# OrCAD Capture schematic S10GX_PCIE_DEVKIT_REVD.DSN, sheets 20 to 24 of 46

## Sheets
20 Flash Memory: size C
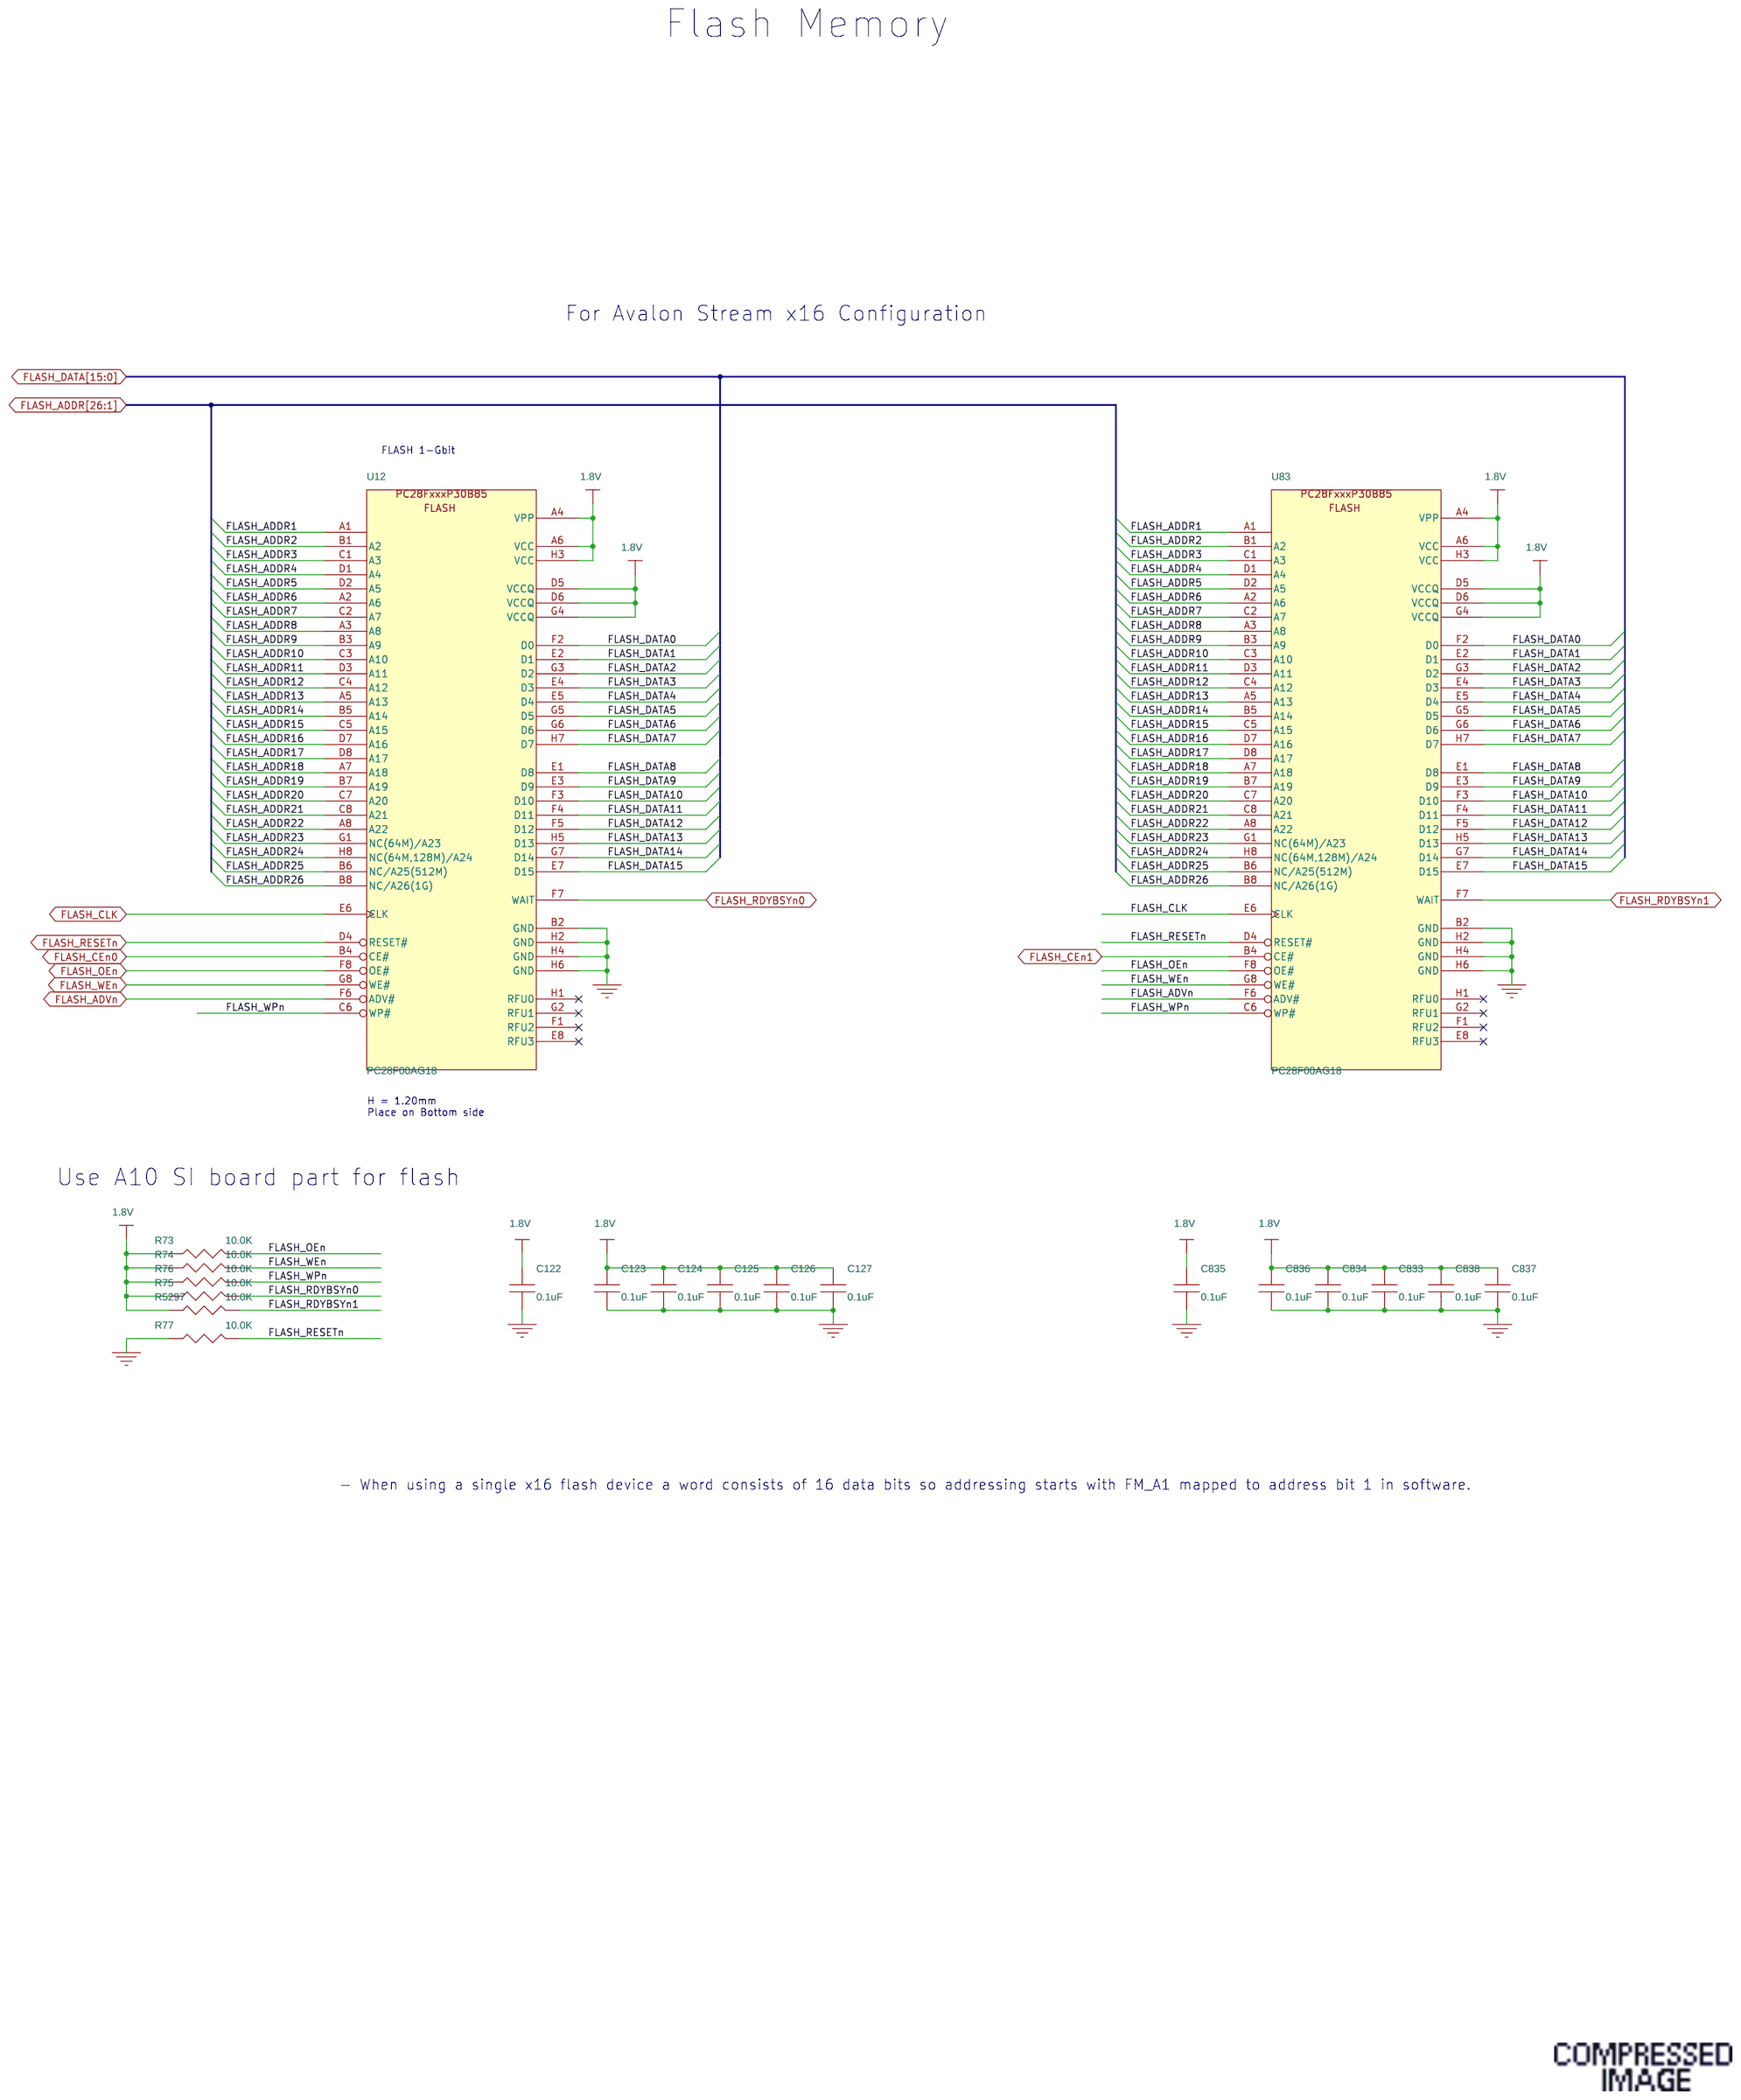
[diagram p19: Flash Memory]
21 10/100/1000 Ethernet Phy: size C
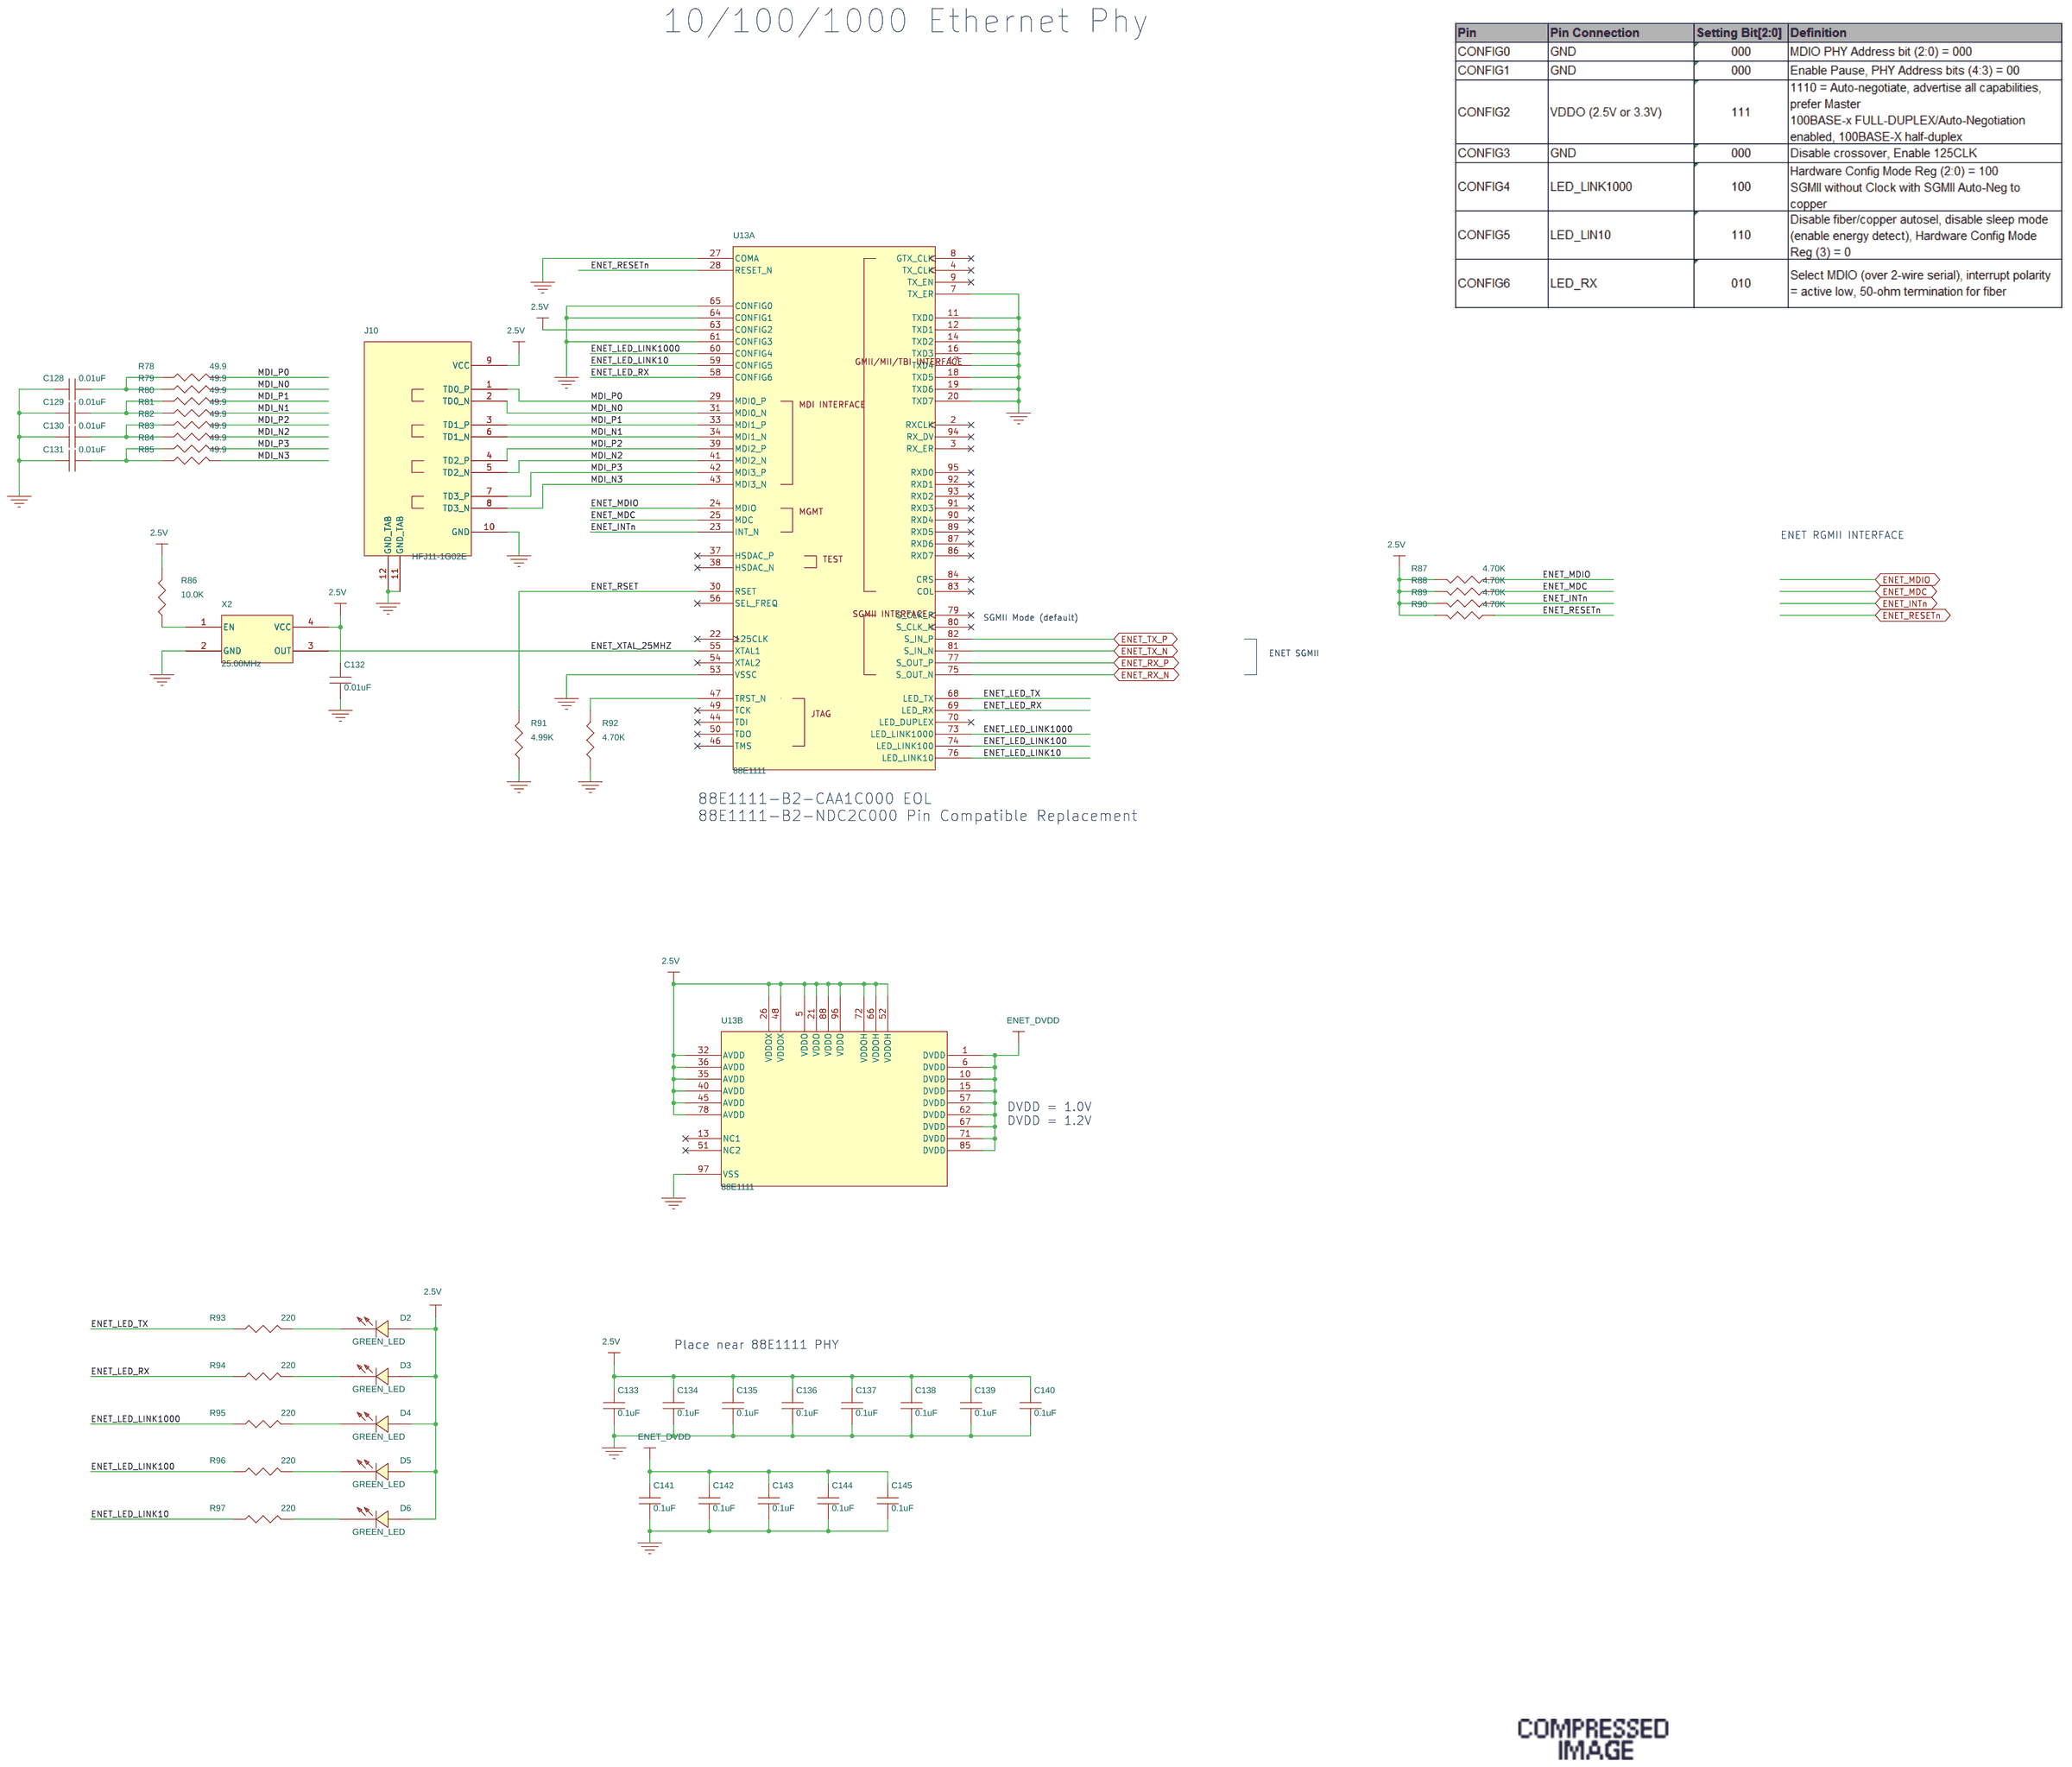
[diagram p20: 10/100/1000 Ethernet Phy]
22 HILO Connector Map
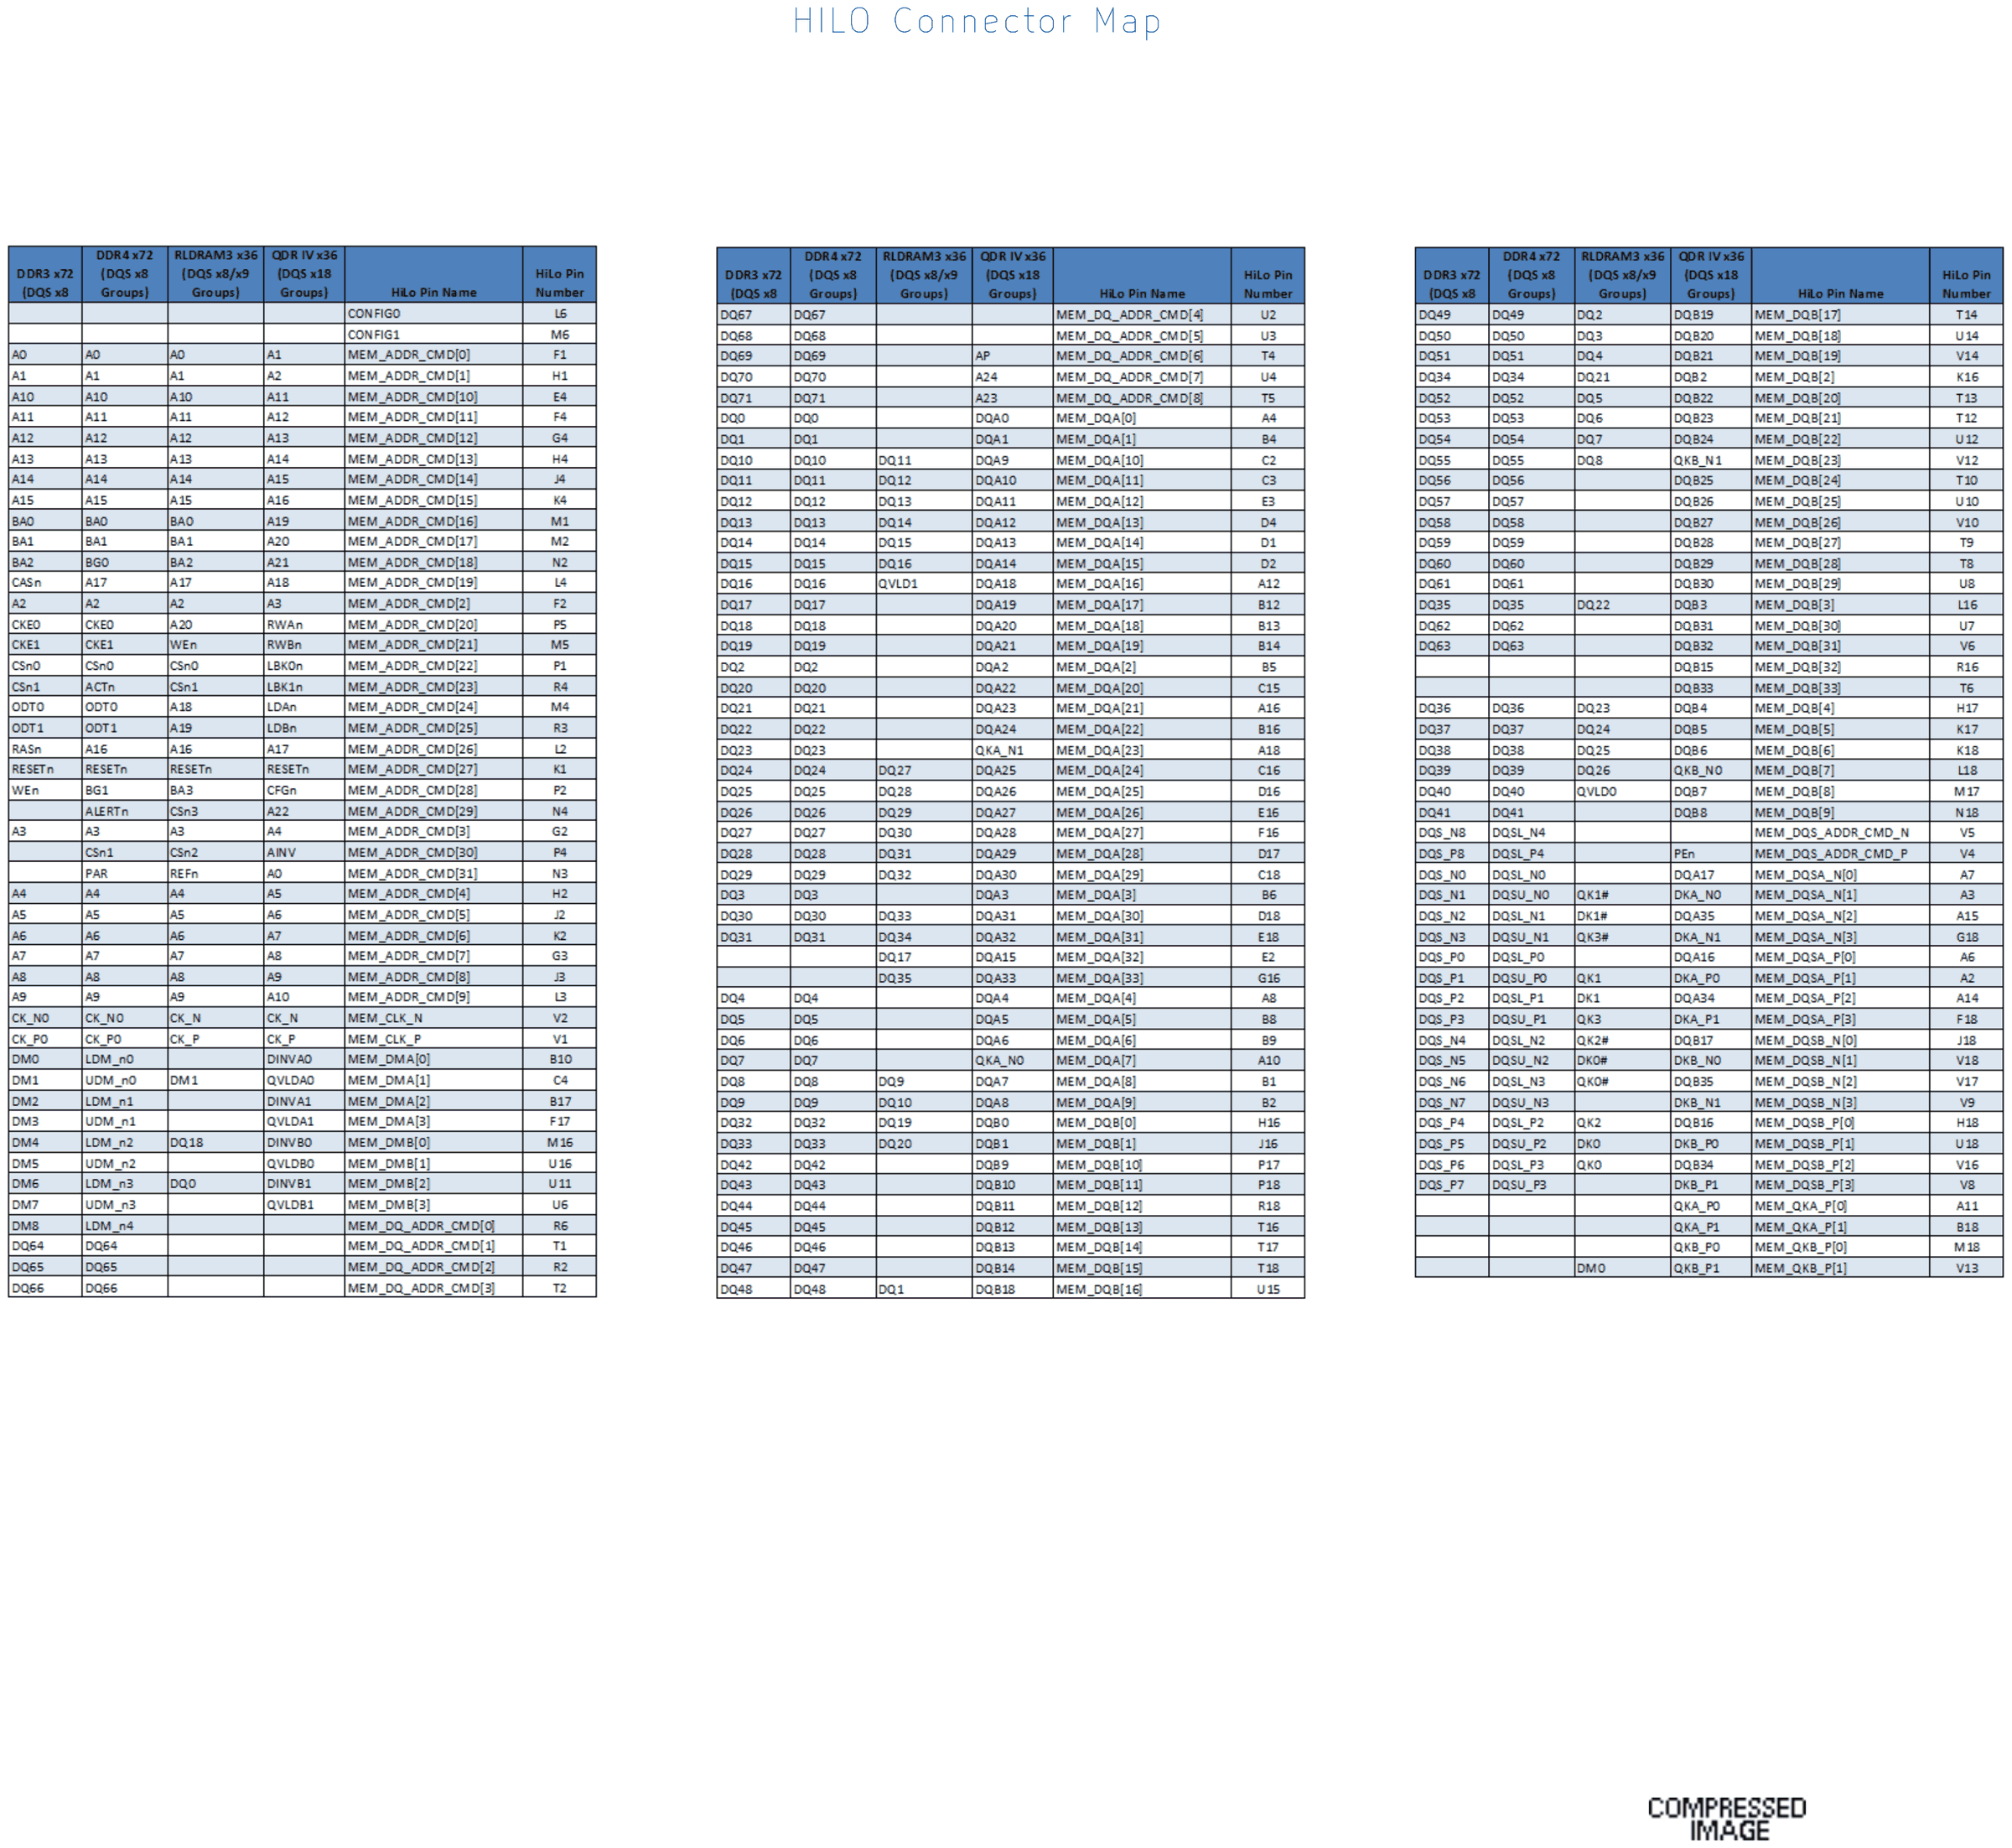
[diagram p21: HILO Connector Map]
23 HILO Memory Interface: size C
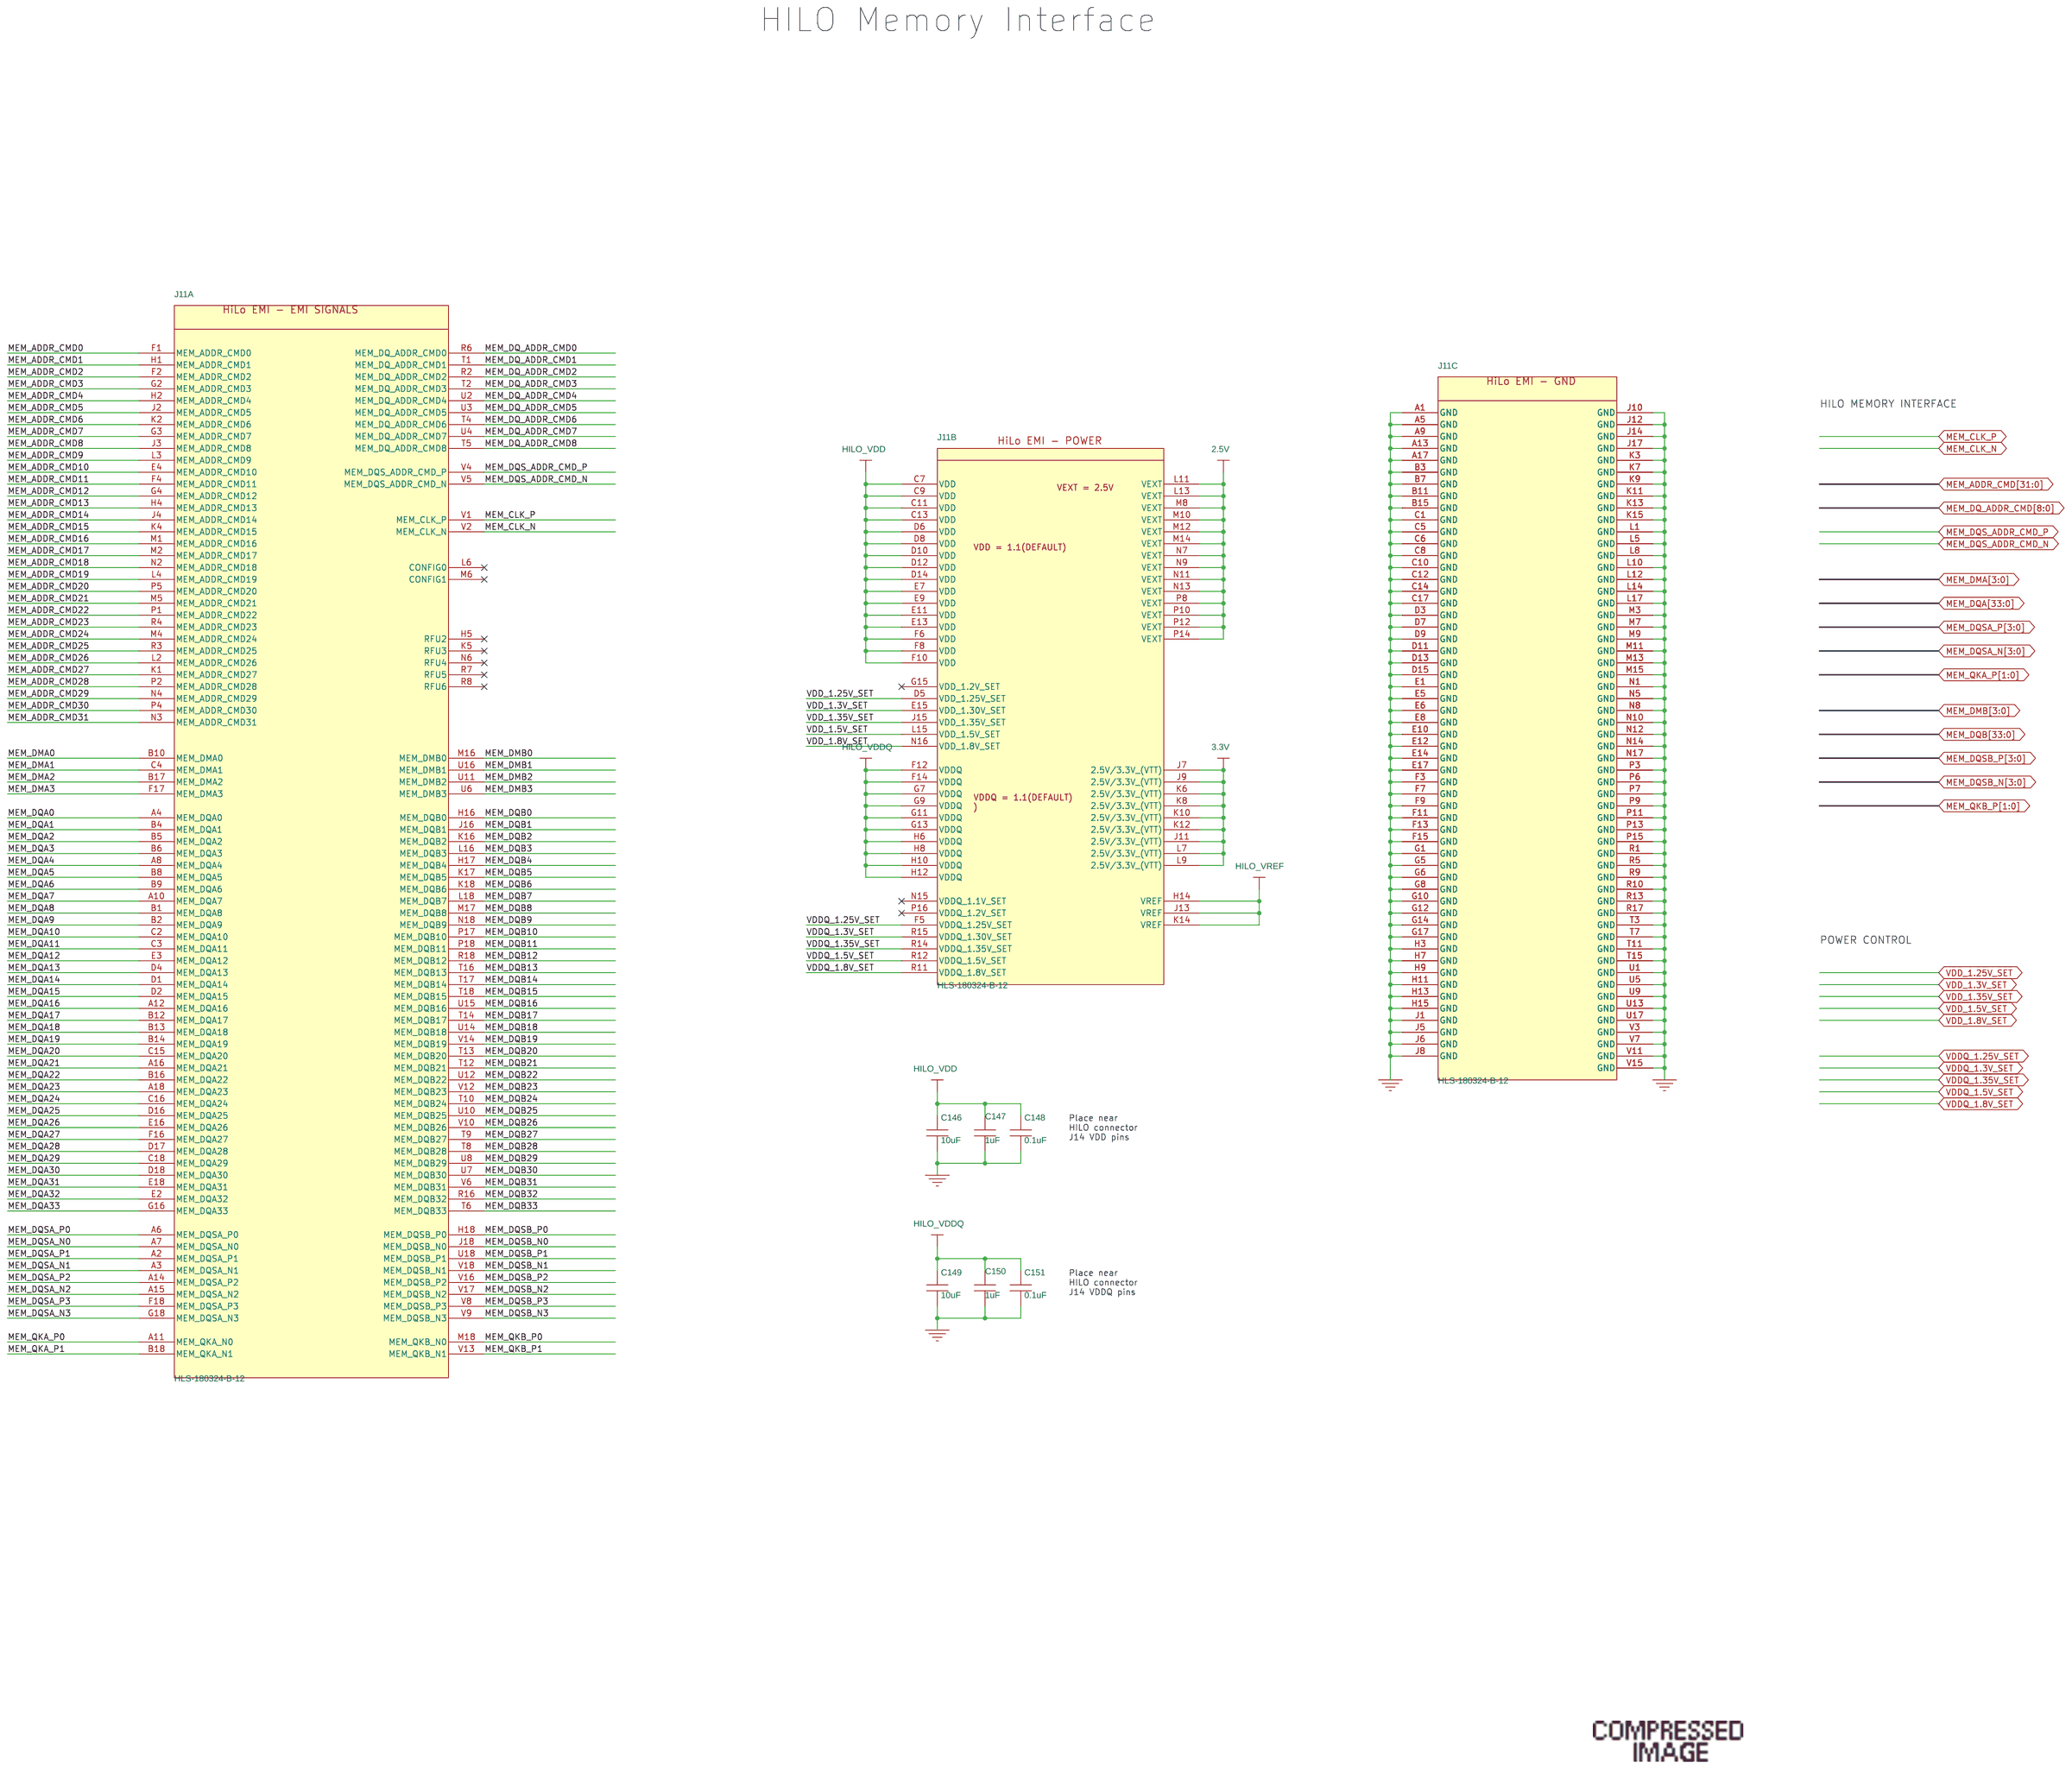
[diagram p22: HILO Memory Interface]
24 Display Port (x4): size C
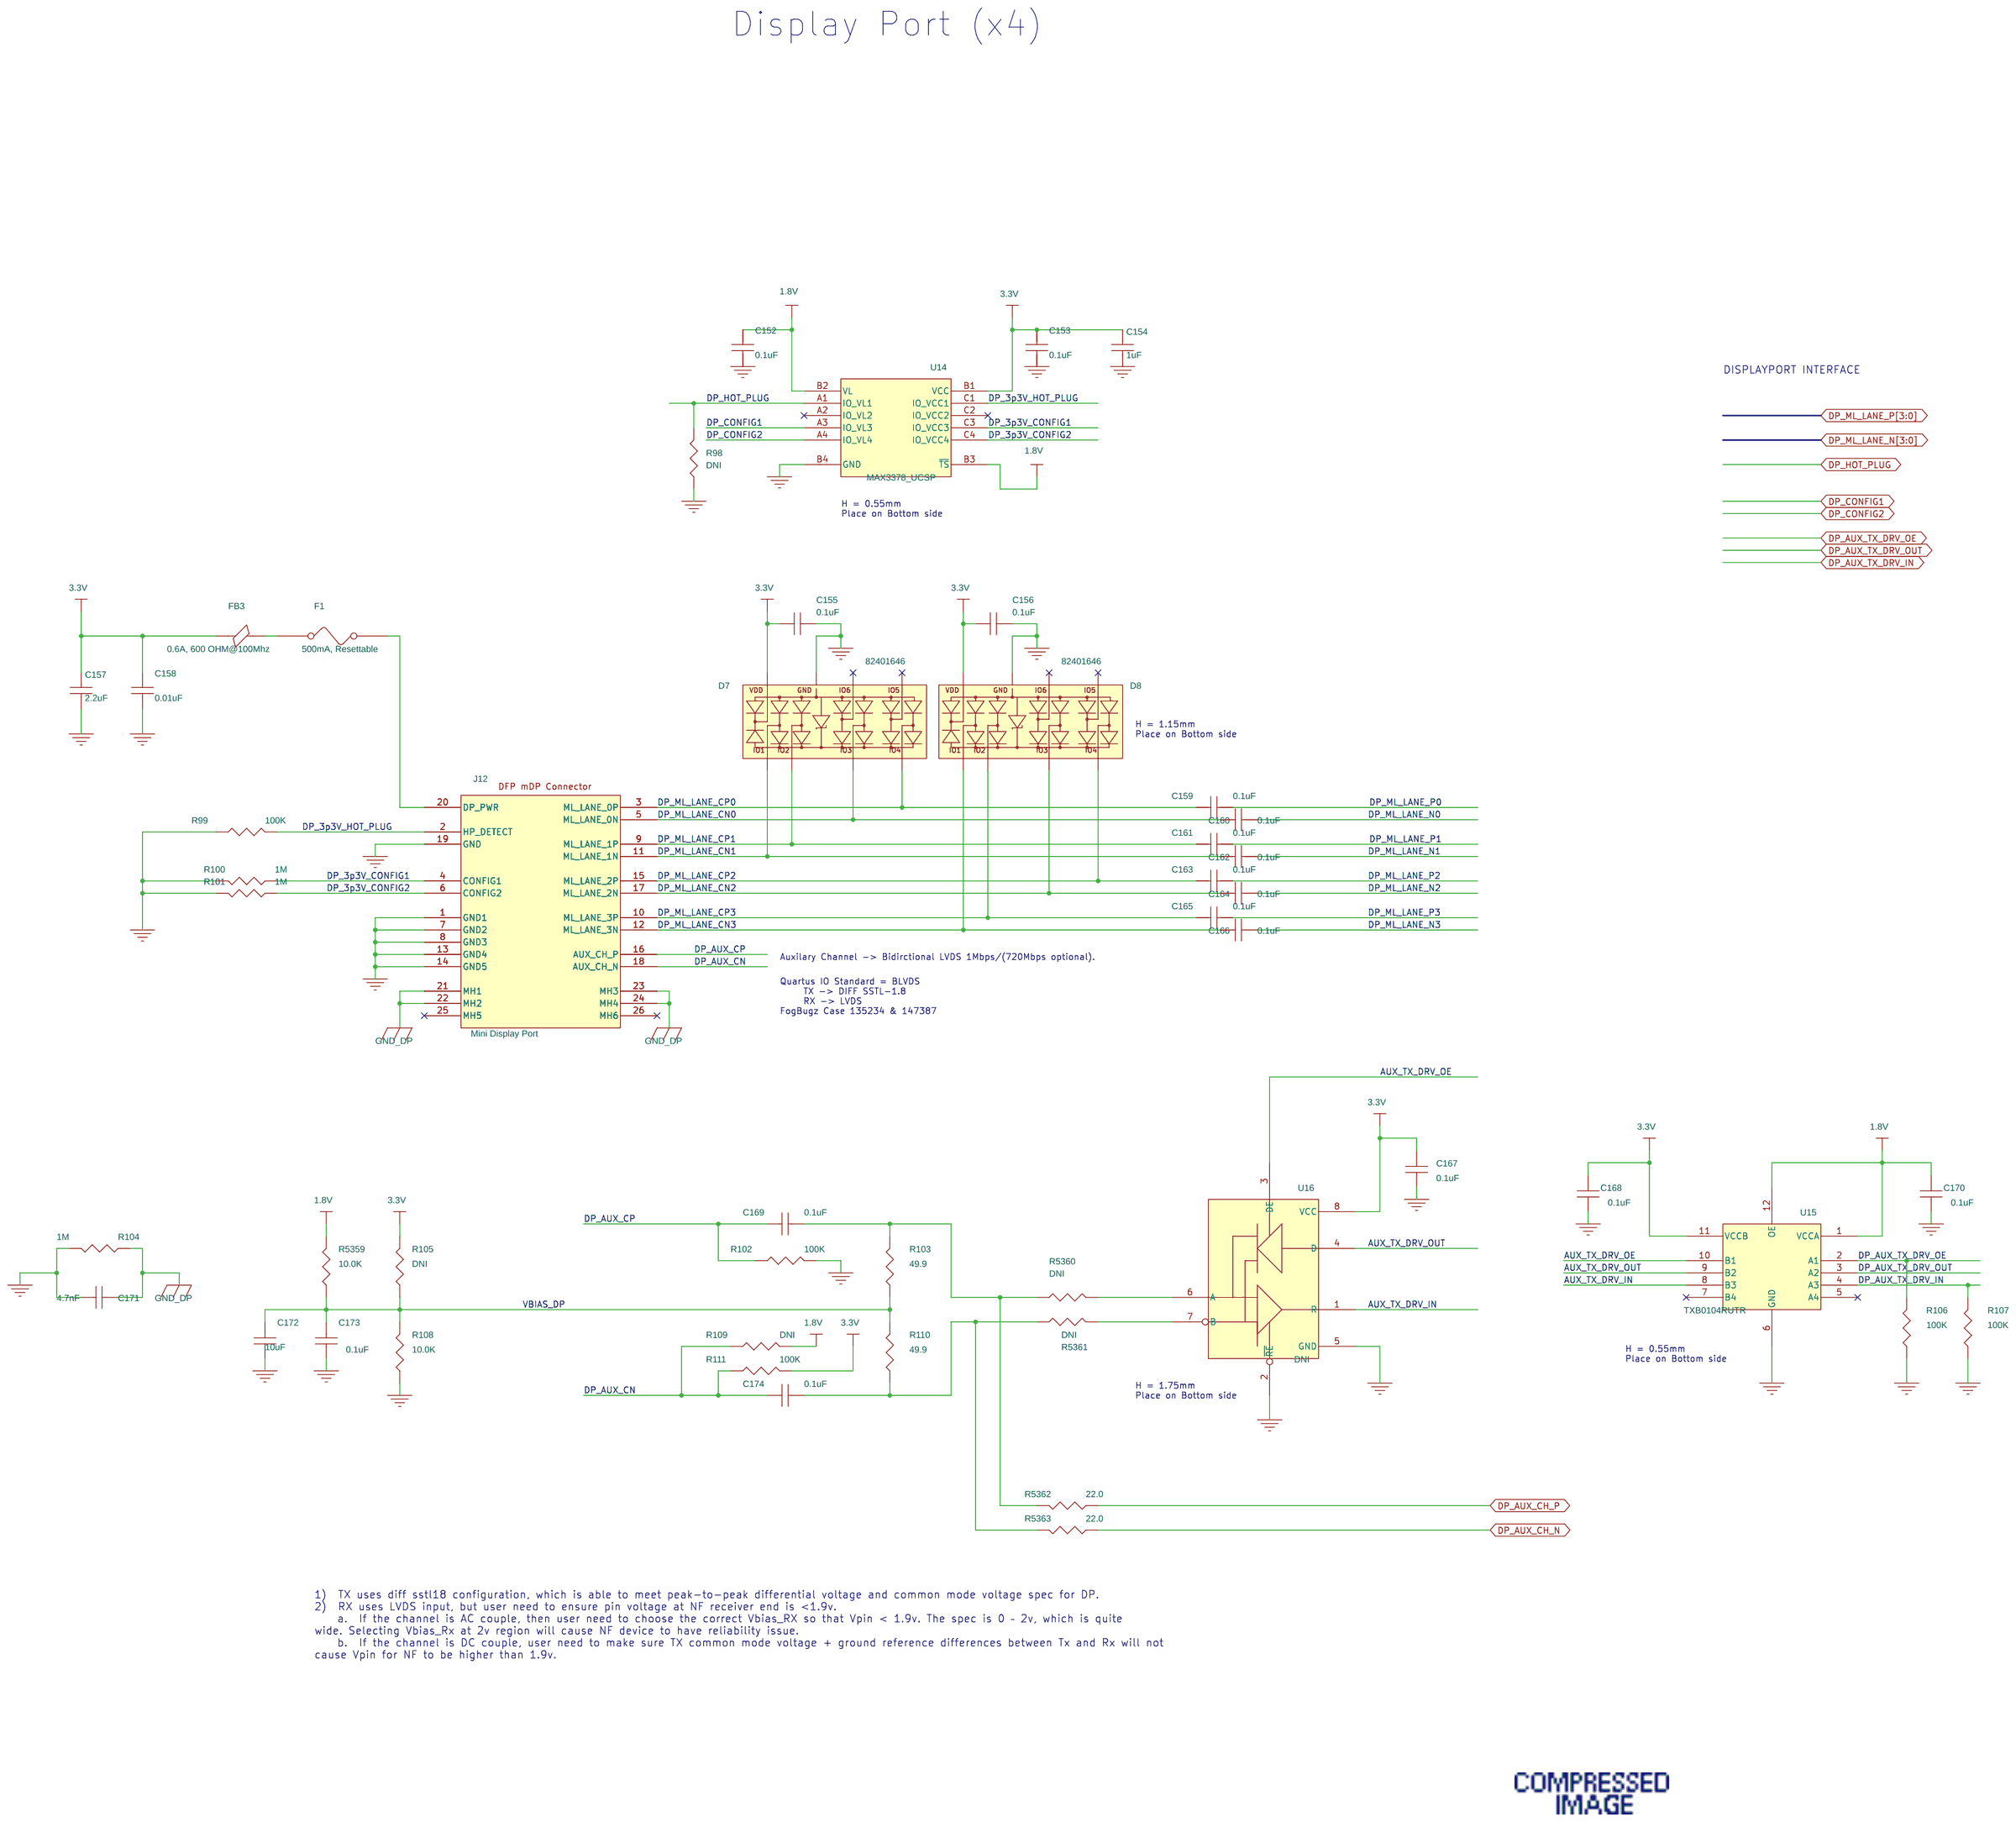
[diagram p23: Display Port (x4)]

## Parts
sheet 10/100/1000 Ethernet Phy
C128  0.01uF  [0402]
C129  0.01uF  [0402]
C130  0.01uF  [0402]
C131  0.01uF  [0402]
C132  0.01uF  [0402]
C133  0.1uF  [0402]
C134  0.1uF  [0402]
C135  0.1uF  [0402]
C136  0.1uF  [0402]
C137  0.1uF  [0402]
C138  0.1uF  [0402]
C139  0.1uF  [0402]
C140  0.1uF  [0402]
C141  0.1uF  [0402]
C142  0.1uF  [0402]
C143  0.1uF  [0402]
C144  0.1uF  [0402]
C145  0.1uF  [0402]
D2  GREEN_LED  [LED_0603]
D3  GREEN_LED  [LED_0603]
D4  GREEN_LED  [LED_0603]
D5  GREEN_LED  [LED_0603]
D6  GREEN_LED  [LED_0603]
J10  HFJ11-1G02E  [rj45]
R78  49.9  [0402]
R79  49.9  [0402]
R80  49.9  [0402]
R81  49.9  [0402]
R82  49.9  [0402]
R83  49.9  [0402]
R84  49.9  [0402]
R85  49.9  [0402]
R86  10.0K  [0402]
R87  4.70K  [0402]
R88  4.70K  [0402]
R89  4.70K  [0402]
R90  4.70K  [0402]
R91  4.99K  [0402]
R92  4.70K  [0402]
R93  220  [0402]
R94  220  [0402]
R95  220  [0402]
R96  220  [0402]
R97  220  [0402]
U13  88E1111  [BCC96]  (sections A,B)
X2  25.00MHz  [XTAL_SG310]
sheet Display Port (x4)
C152  0.1uF  [0402]
C153  0.1uF  [0402]
C154  1uF  [0402]
C155  0.1uF  [0402]
C156  0.1uF  [0402]
C157  2.2uF  [0603]
C158  0.01uF  [0402]
C159  0.1uF  [0402]
C160  0.1uF  [0402]
C161  0.1uF  [0402]
C162  0.1uF  [0402]
C163  0.1uF  [0402]
C164  0.1uF  [0402]
C165  0.1uF  [0402]
C166  0.1uF  [0402]
C167  0.1uF  [0402]
C168  0.1uF  [0402]
C169  0.1uF  [0402]
C170  0.1uF  [0402]
C171  4.7nF  [0402]
C172  10uF  [0603]
C173  0.1uF  [0402]
C174  0.1uF  [0402]
D7  82401646  [wurth_msop8]
D8  82401646  [wurth_msop8]
F1  500mA, Resettable  [0805]
FB3  0.6A, 600 OHM@100Mhz  [0805]
J12  Mini Display Port  [Mini_DP]
R98  DNI  [0402]
R99  100K  [0402]
R100  1M  [0402]
R101  1M  [0402]
R102  100K  [0402]
R103  49.9  [0402]
R104  1M  [0402]
R105  DNI  [0402]
R106  100K  [0402]
R107  100K  [0402]
R108  10.0K  [0402]
R109  DNI  [0402]
R110  49.9  [0402]
R111  100K  [0402]
R5359  10.0K  [0402]
R5360  DNI  [0402]
R5361  DNI  [0402]
R5362  22.0  [0402]
R5363  22.0  [0402]
U14  MAX3378_UCSP  [UCSP-12]
U15  TXB0104RUTR  [UPFN-12]
U16  DNI  [SOIC-8]
sheet Flash Memory
C122  0.1uF  [0402]
C123  0.1uF  [0402]
C124  0.1uF  [0402]
C125  0.1uF  [0402]
C126  0.1uF  [0402]
C127  0.1uF  [0402]
C833  0.1uF  [0402]
C834  0.1uF  [0402]
C835  0.1uF  [0402]
C836  0.1uF  [0402]
C837  0.1uF  [0402]
C838  0.1uF  [0402]
R73  10.0K  [0402]
R74  10.0K  [0402]
R75  10.0K  [0402]
R76  10.0K  [0402]
R77  10.0K  [0402]
R5297  10.0K  [0402]
U12  PC28F00AG18  [F64_10x8]
U83  PC28F00AG18  [F64_10x8]
sheet HILO Memory Interface
C146  10uF  [0603]
C147  1uF  [0402]
C148  0.1uF  [0402]
C149  10uF  [0603]
C150  1uF  [0402]
C151  0.1uF  [0402]
J11  HLS-180324-B-12  [ISI_HILO-SKT_324-KEYED]  (sections A,B,C)

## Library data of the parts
C128-C132 = CAP: CAP - CER, 10NF, 50V, +/-10%, X7R, 0402 SMD; Dielectric: X5R; Item Num: P03-16318R; Lead Free Status: Yes; Manufacturer: Murata; Manufacturer Part Num: GRM155R71H103KA88D; Manufacturer's Part No.: GRM155R71H103KA88D; Num Pins: 2; Part Class: CAPACITORS; Price: 0.07; RoHS Compliant: Yes; Tolerance: 10%
C133-C145 C155 C156 C159-C170 C173 C174 = CAP: CAP - CERAMIC,  0.1UF 0402 25VDC Y5V; AGILE_LINK: http://sj-agile9app/Agile/PLMServlet?action=OpenEmailObject&classid=10000&objid=213459527; Item Num: P03-15057R; LIFECYCLE_PHASE: Active; Lead Free Status: Lead Free; MFR_LIFECYCLE: Active; Manufacturer: Murata; Manufacturer Part Num: GRM155F51E104ZA01D; Num Pins: 2; PART_SUBCLASS: CAPACITORS; Part Class: CAPACITORS; RATED_VOLTAGE: 25V; RoHS Compliant: RoHS Compliant; TOLERANCE: +80%/-20%
D2-D6 = LED_WURTH: LED - BRIGHT GREEN, VF=2V, IF=0.03A, 0603; Item Num: P09-21344R; LIFECYCLE_PHASE: Active; Lead Free Status: Lead Free; Manufacturer: Wurth Electroniks; Manufacturer Part Num: 150060VS75000; Num Pins: 2; PART_SUBCLASS: LEDS; Part Class: LEDS; RoHS Compliant: RoHS Compliant
J10 = HFJ11-1G02E: CONN RJ-45 SINGLE PORT 10/100/1000 BASET INTEGRATED MAGNETICS 10 PIN; Item Num: P23-35065R; Lead Free Status: No; Manufacturer: Halo Electronics, Inc.; Manufacturer Part Num: HFJ11-1G02ERL; Num Pins: 10; Part Class: Connectors; Price: 10; RoHS Compliant: Yes
R78-R85 R103 R110 = RESISTOR: RES, 49.9 OHMS, 1%, 1/16W, 0402; Item Num: P02-14101R; Lead Free Status: Yes; Manufacturer: NIC Components Corp.; Manufacturer Part Num: NRC04F49R9TRF; Num Pins: 2; Part Class: Resistors; Price: 0
R73-R77 R86 R108 R5297 R5359 = RESISTOR: RES,10.0K OHMS,1.0%,1/16W, 0402; AGILE_LINK: http://sj-agile9app/Agile/PLMServlet?action=OpenEmailObject&classid=10000&objid=146548997; Item Num: P02-11364R; LIFECYCLE_PHASE: Active; Lead Free Status: No; MFR_LIFECYCLE: Active; Manufacturer: Panasonic; Manufacturer Part Num: ERJ-2RKF1002X; Num Pins: 2; PART_SUBCLASS: RESISTORS; POWER: 1/16W; RoHS Compliant: Yes; TOLERANCE: +/-1%
R87-R90 R92 = RESISTOR: RES,4.70K OHMS,1.0%,1/16W,0402; AGILE_LINK: http://sj-agile9app/Agile/PLMServlet?action=OpenEmailObject&classid=10000&objid=146753272; Item Num: P02-11384R; LIFECYCLE_PHASE: Active; Lead Free Status: No; MFR_LIFECYCLE: Active; Manufacturer: Vishay; Manufacturer Part Num: CRCW04024K70FKED; Num Pins: 2; PART_SUBCLASS: RESISTORS; POWER: 1/16W; RESISTANCE: 4.7K; RoHS Compliant: Yes; TOLERANCE: +/-1%
R91 = RESISTOR: RES 4.99K OHM 1/16W 1% 0402 SMD; Item Num: P02-14129R; Lead Free Status: Yes; Manufacturer: Panasonic; Manufacturer Part Num: ERJ-2RKF4991X; Num Pins: 2; Part Class: Resistors; Price: 0
R93-R97 = RESISTOR: RES, 220 OHMS, 5%, 1/16W, 0402; Item Num: P02-14107R; Lead Free Status: No; Manufacturer: Panasonic; Manufacturer Part Num: ERJ-2GEJ221X; Num Pins: 2; Part Class: Resistors; Price: 0
U13 = 88E1111_0: IC GIGE XCVR 10/100/1000BASE-T 2.5V 96-PIN BCC; Item Num: P01-13032R; Lead Free Status: Yes; Manufacturer: Marvell Semiconductor, Inc.; Manufacturer Part Num: 88E1111-B2-NDC2C000; Num Pins: 96; Part Class: ICs; Price: 0; RoHS Compliant: Yes
X2 = OSC_ALT: CRYSTAL, 25.000MHZ OSC, CMOS, 2.5V, SMT 3.2MM X 2.5MM, +/-50PPM; AGILE_LINK: http://sj-agile9app/Agile/PLMServlet?action=OpenEmailObject&classid=10000&objid=259526610; Item Num: P07-19194R; LIFECYCLE_PHASE: Preliminary; Lead Free Status: Lead Free; MFR_LIFECYCLE: Active; Manufacturer: Epson; Manufacturer Part Num: SG-310SDF 25.0000M-B3; Num Pins: 4; PART_SUBCLASS: CRYSTALS; RoHS Compliant: RoHS Compliant
C152 C153 = CAP: CAP - CERAMIC,  0.1UF 0402 25VDC Y5V; Dielectric: Y5V; Item Num: P03-15057R; LIFECYCLE_PHASE: Active; Lead Free Status: Lead Free; MFR_LIFECYCLE: Active; Manufacturer: Murata; Manufacturer Part Num: GRM155F51E104ZA01D; Num Pins: 2; PART_SUBCLASS: CAPACITORS; Part Class: CAPACITORS; RATED_VOLTAGE: 25V; RoHS Compliant: RoHS Compliant; Tolerance: +80%/-20%
C154 = CAP: CAP - CER, 1uF, 10V, +/-10%, X5R, 0402; Item Num: P03-15479R; Lead Free Status: Yes; Manufacturer: Murata; Manufacturer Part Num: GRM155R61A105KE15D; Num Pins: 2; Part Class: CAPACITORS; RoHS Compliant: Yes
C157 = CAP: CAP, CERAMIC, 2.2UF, 10%, 10VDC, X5R, 0603; AGILE_LINK: http://sj-agile9app/Agile/PLMServlet?action=OpenEmailObject&classid=10000&objid=256999866; Device: C40; Item Num: P03-15213R; LIFECYCLE_PHASE: Active; Lead Free Status: Lead Free; MFR_LIFECYCLE: Active; Manufacturer: Murata; Manufacturer Part Num: GRM188R61A225KE34x; Num Pins: 2; PART_SUBCLASS: CAPACITORS; RATED_VOLTAGE: 10V; RoHS Compliant: RoHS Compliant; Supplier Part Num: 490-1545-1-ND; TOLERANCE: +/-10%
C158 = CAP: CAP, CER .01UF 16V X7R 0402; AGILE_LINK: http://sj-agile9app/Agile/PLMServlet?action=OpenEmailObject&classid=10000&objid=242850622; Item Num: P03-15137R; LIFECYCLE_PHASE: Active; MFR_LIFECYCLE: Active; Manufacturer: Murata; Manufacturer Part Num: GRM155R71C103KA01D; Num Pins: 2; PACKAGING: Tape & Reel (TR); PART_SUBCLASS: CAPACITORS; RATED_VOLTAGE: 16V; RoHS Compliant: RoHS Compliant; TOLERANCE: +/-10%
C171 = CAP: CAP - CER 4700PF 50V 10% X7R 0402; AGILE_LINK: http://sj-agile9app/Agile/PLMServlet?action=OpenEmailObject&classid=10000&objid=215384813; Item Num: P03-15074R; LIFECYCLE_PHASE: Active; Lead Free Status: Lead Free; MFR_LIFECYCLE: Active; Manufacturer: Murata; Manufacturer Part Num: GRM155R71H472KA01D; Num Pins: 2; PACKAGING: Tape & Reel (TR); PART_SUBCLASS: CAPACITORS; RATED_VOLTAGE: 50V; RoHS Compliant: RoHS Compliant; Supplier Part Num: GRM155R71H472KA01D; Tolerance: +/-10%
C146 C149 C172 = CAP: CAP - CER 10UF 6.3V 20% X5R 0603; Item Num: P03-15733R; Lead Free Status: Lead Free; Manufacturer: Murata; Manufacturer Part Num: GRM188R60J106ME47X; Num Pins: 2; PART_SUBCLASS: CAPACITORS; Part Class: CAPACITORS; RoHS Compliant: RoHS Compliant
D7 D8 = 82401646: DIODE - ULTRA LOW CAPACITANCE ESD ARRAY, 0.3PF IO TO GND, 0.05PF IO TO IO, MSOP-8L; Item Num: P08-20757R; Lead Free Status: Yes; Manufacturer: Wurth; Num Pins: 8; RoHS Compliant: Yes
F1 = FUSE: FUSE - PTC RESTTBLE 0.20A 9V CHIP 0805; Item Num: P12-27075R; Lead Free Status: Yes; Manufacturer: Bel Fuse Inc; Manufacturer Part Num: 0ZCE0020FF2G; Num Pins: 2; Part Class: Fuse; Price: 0; RoHS Compliant: Yes
FB3 = BEAD_FERRITE_SM: FERRITE BEAD 600 OHM 0805 1LN; Item Num: P04-17174R; LIFECYCLE_PHASE: Active; MFR_LIFECYCLE: Active; Manufacturer: Murata; Manufacturer Part Num: BLM21AG601SN1D; Num Pins: 2; PART_SUBCLASS: INDUCTORS; Part Class: Inductors; RoHS Compliant: Yes
J12 = Mini_Display_Port: CONN - MINI-DISPLAY PORT 20-PIN RECEPTACLE, RIGHT ANGLE, SMT; Item Num: P23-38747R; Manufacturer: TE Connectivity AMP Connectors; Manufacturer Part Num: 2129320-3; Manufacturer Part Number: 2129320-3
R98 = RESISTOR: RES, 560 OHM, 5%, 1/16W, 0402, SMD; Item Num: P02-14928R; Lead Free Status: Yes; Manufacturer: Panasonic; Manufacturer Part Num: ERJ-2GEJ561x; Num Pins: 2; Part Class: RESISTORS; Price: 0; RoHS Compliant: Yes
R99 R102 R106 R107 R109 R111 = RESISTOR: RES,100K OHMS,1.0%,1/16W,0402; Item Num: P02-11386R; Lead Free Status: No; Manufacturer: Panasonic; Manufacturer Part Num: ERJ-2RKF1003X; Num Pins: 2; Part Class: Resistors; Price: 0; RoHS Compliant: Yes
R100 R101 R104 = RESISTOR: RES 1.00M OHM 1/16W 1% 0402 SMD; Item Num: P02-14034R; LIFECYCLE_PHASE: Active; Lead Free Status: Lead Free; MFR_LIFECYCLE: Active; Manufacturer: Panasonic; Manufacturer Part Num: ERJ-2RKF1004X; Num Pins: 2; Package: SMD; RoHS Compliant: RoHS Compliant; TOLERANCE: +/-1%
R105 = RESISTOR: RES,10.0K OHMS,1.0%,1/16W, 0402; AGILE_LINK: http://sj-agile9app/Agile/PLMServlet?action=OpenEmailObject&classid=10000&objid=146548997; Item Num: P02-11364R; LIFECYCLE_PHASE: Active; Lead Free Status: No; MFR_LIFECYCLE: Active; Manufacturer: Panasonic; Manufacturer Part Num: ERJ-2RKF1002X; Num Pins: 2; PART_SUBCLASS: RESISTORS; POWER: 1/16W; RESISTANCE: 10.0K; RoHS Compliant: Yes; TOLERANCE: +/-1%
R5360 R5361 = RESISTOR: RES ZERO OHM 1/16W 5% 0402 SMD; Altera Part No.: P02-14020R; Item Num: P02-14020R; LIFECYCLE_PHASE: Active; Lead Free Status: No; MFR_LIFECYCLE: Active; Manufacturer: Panasonic; Manufacturer Part Num: ERJ-2GE0R00X; Num Pins: 2; PART_SUBCLASS: RESISTORS; POWER: 1/16W; Part Class: RESISTORS; Price: 0; RESISTANCE: 0; RoHS Compliant: RoHS Compliant; Tolerance: +/-5%
R5362 R5363 = RESISTOR: RES - 22.0 OHM, 1/16W, 1%, 0402 SMD; Item Num: P02-16269R; Lead Free Status: Yes; Manufacturer: Panasonic; Manufacturer Part Num: ERJ-2RKF22R0X; Num Pins: 2; Part Class: Resistors; Price: 0
U14 = MAX3378_12UCSP: IC - QUAD LOW-VOLTAGE LEVEL TRANSLATOR, +/- 15KV, ESD-PROTECTED, 1UA, 8-16MBPS, 12-UCSP (1.5X2)MM; Item Num: P01-17875R; Lead Free Status: Yes; Manufacturer: Maxim Integrated Products, Inc.; Manufacturer Part Num: MAX3378EEBC+; Num Pins: 12; Part Class: ICs; RoHS Compliant: Yes
U15 = TXB0104RUTR: IC VOLT-LEVEL TRANSLATOR 12UQFN; Item Num: P01-18068R; Manufacturer: Texas Instruments
U16 = SN65MLVD200D: IC DIFF LINE DRVR/RCVR HS 8-SOIC; Item Num: P01-18069R; Manufacturer: Texas Instruments
C122-C127 C833-C838 = CAP: CAP - CERAMIC,  0.1UF 0402 25VDC Y5V; Dielectric: X5R; Item Num: P03-15057R; LIFECYCLE_PHASE: Active; Lead Free Status: Lead Free; Manufacturer: Murata; Manufacturer Part Num: GRM155F51E104ZA01D; Num Pins: 2; Part Class: CAPACITORS; Price: 0.07; RoHS Compliant: RoHS Compliant; Tolerance: +80%/-20%
U12 U83 = PC28FxxxP30B85_1: ICS - 1GBIT STRATA FLASH, 16-BIT DATA, VCC=VCCQ=1.7V-2.0V, 64-BALL EASY BGA (10MM X 8MM); Item Num: P01-17846R; Lead Free Status: Yes; Manufacturer: Micron; Manufacturer Part Num: PC28F00AG18FF; Num Pins: 64; Part Class: ICs; RoHS Compliant: Yes
C147 C150 = CAP: CAP - CER, 1UF, 25V, 10%, X5R, 0402; Item Num: P03-17662R; Lead Free Status: Yes; Manufacturer: TDK Electronics; Manufacturer Part Num: CGB2A1X5R1E105K033BC; Num Pins: 2; Part Class: Capacitors; Price: 0; RoHS Compliant: Yes
C148 C151 = CAP: CAP - CERAMIC,  0.1UF 0402 25VDC Y5V; Dielectric: Y5V; Item Num: P03-15057R; LIFECYCLE_PHASE: Active; Lead Free Status: Lead Free; MFR_LIFECYCLE: Active; Manufacturer: Murata; Manufacturer Part Num: GRM155F51E104ZA01D; Num Pins: 2; PART_SUBCLASS: CAPACITORS; Part Class: CAPACITORS; RATED_VOLTAGE: 25V; RoHS Compliant: RoHS Compliant; TOLERANCE: +80%/-20%
J11 = EMI_HLS-180324-B-12: CONN - HILO 324-PIN + 2-ALLIGNMENT PINS, 1MM PITCH; Item Num: P23-38580R; Lead Free Status: Yes; Manufacturer: Interconnect Systems, Inc (ISI); Num Pins: 326; Part Class: Connectors; RoHS Compliant: Yes

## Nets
1.8V: C122.1 C123.1 C124.1 C125.1 C126.1 C127.1 C152.1 C170.2 C833.1 C834.1 C835.1 C836.1 C837.1 C838.1 R73.1 R74.1 R75.1 R76.1 R109.2 R5297.1 R5359.2 U12.A4(VPP) U12.A6(VCC) U12.D5(VCCQ) U12.D6(VCCQ) U12.G4(VCCQ) U12.H3(VCC) U14.B2(VL) U14.B3(~{TS}) U15.1(VCCA) U15.12(OE) U83.A4(VPP) U83.A6(VCC) U83.D5(VCCQ) U83.D6(VCCQ) U83.G4(VCCQ) U83.H3(VCC) ; also on sheet 6 9 15 16 17 19 27 28 29 30 31 39 45
2.5V: C132.1 C133.1 C134.1 C135.1 C136.1 C137.1 C138.1 C139.1 C140.1 D2.A(ANODE) D3.A(ANODE) D4.A(ANODE) D5.A(ANODE) D6.A(ANODE) J10.9(VCC) J11.L11(VEXT) J11.L13(VEXT) J11.M8(VEXT) J11.M10(VEXT) J11.M12(VEXT) J11.M14(VEXT) J11.N7(VEXT) J11.N9(VEXT) J11.N11(VEXT) J11.N13(VEXT) J11.P8(VEXT) J11.P10(VEXT) J11.P12(VEXT) J11.P14(VEXT) R86.2 R87.2 R88.2 R89.2 R90.2 U13.5(VDDO) U13.21(VDDO) U13.26(VDDOX) U13.32(AVDD) U13.35(AVDD) U13.36(AVDD) U13.40(AVDD) U13.45(AVDD) U13.48(VDDOX) U13.52(VDDOH) U13.63(CONFIG2) U13.66(VDDOH) U13.72(VDDOH) U13.78(AVDD) U13.88(VDDO) U13.96(VDDO) X2.4(VCC) ; also on sheet 18 19 28 29 31 32 43 46
3.3V: C153.1 C154.1 C155.1 C156.1 C157.1 C158.1 C167.2 C168.2 D7.8 D8.8 FB3.2 J11.J7(2.5V/3.3V_(VTT)) J11.J9(2.5V/3.3V_(VTT)) J11.J11(2.5V/3.3V_(VTT)) J11.K6(2.5V/3.3V_(VTT)) J11.K8(2.5V/3.3V_(VTT)) J11.K10(2.5V/3.3V_(VTT)) J11.K12(2.5V/3.3V_(VTT)) J11.L7(2.5V/3.3V_(VTT)) J11.L9(2.5V/3.3V_(VTT)) R105.2 R111.2 U14.B1(VCC) U15.11(VCCB) U16.8(VCC) ; also on sheet 9 17 18 19 25 27 28 29 30 32 34
GND: C122.2 C123.2 C124.2 C125.2 C126.2 C127.2 C128.1 C129.1 C130.1 C131.1 C132.2 C133.2 C134.2 C135.2 C136.2 C137.2 C138.2 C139.2 C140.2 C141.2 C142.2 C143.2 C144.2 C145.2 C146.2 C147.2 C148.2 C149.2 C150.2 C151.2 C152.2 C153.2 C154.2 C155.2 C156.2 C157.2 C158.2 C167.1 C168.1 C170.1 C171.1 C172.1 C173.1 C833.2 C834.2 C835.2 C836.2 C837.2 C838.2 D7.7 D8.7 J10.10(GND) J10.11(GND_TAB) J10.12(GND_TAB) J11.A1(GND) J11.A5(GND) J11.A9(GND) J11.A13(GND) J11.A17(GND) J11.B3(GND) J11.B7(GND) J11.B11(GND) J11.B15(GND) J11.C1(GND) J11.C5(GND) J11.C6(GND) J11.C8(GND) J11.C10(GND) J11.C12(GND) J11.C14(GND) J11.C17(GND) J11.D3(GND) J11.D7(GND) J11.D9(GND) J11.D11(GND) J11.D13(GND) J11.D15(GND) J11.E1(GND) J11.E5(GND) J11.E6(GND) J11.E8(GND) J11.E10(GND) J11.E12(GND) J11.E14(GND) J11.E17(GND) J11.F3(GND) J11.F7(GND) J11.F9(GND) J11.F11(GND) J11.F13(GND) J11.F15(GND) J11.G1(GND) J11.G5(GND) J11.G6(GND) J11.G8(GND) J11.G10(GND) J11.G12(GND) J11.G14(GND) J11.G17(GND) J11.H3(GND) J11.H7(GND) J11.H9(GND) J11.H11(GND) J11.H13(GND) J11.H15(GND) J11.J1(GND) J11.J5(GND) J11.J6(GND) J11.J8(GND) J11.J10(GND) J11.J12(GND) J11.J14(GND) J11.J17(GND) J11.K3(GND) J11.K7(GND) J11.K9(GND) J11.K11(GND) J11.K13(GND) J11.K15(GND) J11.L1(GND) J11.L5(GND) J11.L8(GND) J11.L10(GND) J11.L12(GND) J11.L14(GND) J11.L17(GND) J11.M3(GND) J11.M7(GND) J11.M9(GND) J11.M11(GND) J11.M13(GND) J11.M15(GND) J11.N1(GND) J11.N5(GND) J11.N8(GND) J11.N10(GND) J11.N12(GND) J11.N14(GND) J11.N17(GND) J11.P3(GND) J11.P6(GND) J11.P7(GND) J11.P9(GND) J11.P11(GND) J11.P13(GND) J11.P15(GND) J11.R1(GND) J11.R5(GND) J11.R9(GND) J11.R10(GND) J11.R13(GND) J11.R17(GND) J11.T3(GND) J11.T7(GND) J11.T11(GND) J11.T15(GND) J11.U1(GND) J11.U5(GND) J11.U9(GND) J11.U13(GND) J11.U17(GND) J11.V3(GND) J11.V7(GND) J11.V11(GND) J11.V15(GND) J12.1(GND1) J12.7(GND2) J12.8(GND3) J12.13(GND4) J12.14(GND5) J12.19(GND) R77.1 R91.1 R92.1 R98.1 R99.1 R100.1 R101.1 R102.2 R104.2 R106.1 R107.1 R108.1 U12.B2(GND) U12.H2(GND) U12.H4(GND) U12.H6(GND) U13.7(TX_ER) U13.11(TXD0) U13.12(TXD1) U13.14(TXD2) U13.16(TXD3) U13.17(TXD4) U13.18(TXD5) U13.19(TXD6) U13.20(TXD7) U13.27(COMA) U13.53(VSSC) U13.61(CONFIG3) U13.64(CONFIG1) U13.65(CONFIG0) U13.97(VSS) U14.B4(GND) U15.6(GND) U16.2(~{RE}) U16.5(GND) U83.B2(GND) U83.H2(GND) U83.H4(GND) U83.H6(GND) X2.2(GND) ; also on sheet 6 7 8 9 10 11 12 13 14 15 16 17 18 19 25 27 28 29 30 31 32 33 34 35 36 37 38 39 40 41 42 43 44 45 46
GND_DP: C171.2 J12.21(MH1) J12.22(MH2) J12.23(MH3) J12.24(MH4) R104.1
VDD_1.3V_SET: J11.E15(VDD_1.30V_SET) ; also on sheet 42
VDD_1.5V_SET: J11.L15(VDD_1.5V_SET) ; also on sheet 42
VDD_1.8V_SET: J11.N16(VDD_1.8V_SET) ; also on sheet 42
VDD_1.25V_SET: J11.D5(VDD_1.25V_SET) ; also on sheet 42
VDD_1.35V_SET: J11.J15(VDD_1.35V_SET) ; also on sheet 42
VDDQ_1.3V_SET: J11.R15(VDDQ_1.30V_SET) ; also on sheet 42
VDDQ_1.5V_SET: J11.R12(VDDQ_1.5V_SET) ; also on sheet 42
VDDQ_1.8V_SET: J11.R11(VDDQ_1.8V_SET) ; also on sheet 42
VDDQ_1.25V_SET: J11.F5(VDDQ_1.25V_SET) ; also on sheet 42
VDDQ_1.35V_SET: J11.R14(VDDQ_1.35V_SET) ; also on sheet 42
AUX_TX_DRV_IN: U15.8(B3) U16.1(R)
AUX_TX_DRV_OE: U15.10(B1) U16.3(DE)
AUX_TX_DRV_OUT: U15.9(B2) U16.4(D)
DP_3p3V_CONFIG1: J12.4(CONFIG1) R100.2 U14.C3(IO_VCC3)
DP_3p3V_CONFIG2: J12.6(CONFIG2) R101.2 U14.C4(IO_VCC4)
DP_3p3V_HOT_PLUG: J12.2(HP_DETECT) R99.2 U14.C1(IO_VCC1)
DP_AUX_CH_N: R5363.1 ; also on sheet 8
DP_AUX_CH_P: R5362.1 ; also on sheet 8
DP_AUX_CN: C174.1 J12.18(AUX_CH_N) R109.1 R111.1
DP_AUX_CP: C169.1 J12.16(AUX_CH_P) R102.1
DP_AUX_TX_DRV_IN: R107.2 U15.4(A3) ; also on sheet 8
DP_AUX_TX_DRV_OE: R106.2 U15.2(A1) ; also on sheet 8
DP_AUX_TX_DRV_OUT: U15.3(A2) ; also on sheet 8
DP_CONFIG1: U14.A3(IO_VL3) ; also on sheet 8
DP_CONFIG2: U14.A4(IO_VL4) ; also on sheet 8
DP_HOT_PLUG: R98.2 U14.A1(IO_VL1) ; also on sheet 8
DP_ML_LANE_CN0: C160.1 D7.3 J12.5(ML_LANE_0N)
DP_ML_LANE_CN1: C162.1 D7.1 J12.11(ML_LANE_1N)
DP_ML_LANE_CN2: C164.1 D8.3 J12.17(ML_LANE_2N)
DP_ML_LANE_CN3: C166.1 D8.1 J12.12(ML_LANE_3N)
DP_ML_LANE_CP0: C159.1 D7.4 J12.3(ML_LANE_0P)
DP_ML_LANE_CP1: C161.1 D7.2 J12.9(ML_LANE_1P)
DP_ML_LANE_CP2: C163.1 D8.4 J12.15(ML_LANE_2P)
DP_ML_LANE_CP3: C165.1 D8.2 J12.10(ML_LANE_3P)
DP_ML_LANE_N0: C160.2 ; also on sheet 11
DP_ML_LANE_N1: C162.2 ; also on sheet 11
DP_ML_LANE_N2: C164.2 ; also on sheet 11
DP_ML_LANE_N3: C166.2 ; also on sheet 11
DP_ML_LANE_P0: C159.2 ; also on sheet 11
DP_ML_LANE_P1: C161.2 ; also on sheet 11
DP_ML_LANE_P2: C163.2 ; also on sheet 11
DP_ML_LANE_P3: C165.2 ; also on sheet 11
ENET_DVDD: C141.1 C142.1 C143.1 C144.1 C145.1 U13.1(DVDD) U13.6(DVDD) U13.10(DVDD) U13.15(DVDD) U13.57(DVDD) U13.62(DVDD) U13.67(DVDD) U13.71(DVDD) U13.85(DVDD) ; also on sheet 43
ENET_INTn: R89.1 U13.23(INT_N) ; also on sheet 6
ENET_LED_LINK10: R97.1 U13.59(CONFIG5) U13.76(LED_LINK10)
ENET_LED_LINK100: R96.1 U13.74(LED_LINK100)
ENET_LED_LINK1000: R95.1 U13.60(CONFIG4) U13.73(LED_LINK1000)
ENET_LED_RX: R94.1 U13.58(CONFIG6) U13.69(LED_RX)
ENET_LED_TX: R93.1 U13.68(LED_TX)
ENET_MDC: R88.1 U13.25(MDC) ; also on sheet 6
ENET_MDIO: R87.1 U13.24(MDIO) ; also on sheet 6
ENET_RESETn: R90.1 U13.28(RESET_N) ; also on sheet 6
ENET_RSET: R91.2 U13.30(RSET)
ENET_RX_N: U13.75(S_OUT_N) ; also on sheet 8
ENET_RX_P: U13.77(S_OUT_P) ; also on sheet 8
ENET_TX_N: U13.81(S_IN_N) ; also on sheet 8
ENET_TX_P: U13.82(S_IN_P) ; also on sheet 8
ENET_XTAL_25MHZ: U13.55(XTAL1) X2.3(OUT)
FLASH_ADDR1: U12.A1 U83.A1 ; also on sheet 7 19
FLASH_ADDR2: U12.B1(A2) U83.B1(A2) ; also on sheet 7 19
FLASH_ADDR3: U12.C1(A3) U83.C1(A3) ; also on sheet 7 19
FLASH_ADDR4: U12.D1(A4) U83.D1(A4) ; also on sheet 7 19
FLASH_ADDR5: U12.D2(A5) U83.D2(A5) ; also on sheet 7 19
FLASH_ADDR6: U12.A2(A6) U83.A2(A6) ; also on sheet 7 19
FLASH_ADDR7: U12.C2(A7) U83.C2(A7) ; also on sheet 7 19
FLASH_ADDR8: U12.A3(A8) U83.A3(A8) ; also on sheet 7 19
FLASH_ADDR9: U12.B3(A9) U83.B3(A9) ; also on sheet 7 19
FLASH_ADDR10: U12.C3(A10) U83.C3(A10) ; also on sheet 7 19
FLASH_ADDR11: U12.D3(A11) U83.D3(A11) ; also on sheet 7 19
FLASH_ADDR12: U12.C4(A12) U83.C4(A12) ; also on sheet 7 19
FLASH_ADDR13: U12.A5(A13) U83.A5(A13) ; also on sheet 7 19
FLASH_ADDR14: U12.B5(A14) U83.B5(A14) ; also on sheet 7 19
FLASH_ADDR15: U12.C5(A15) U83.C5(A15) ; also on sheet 7 19
FLASH_ADDR16: U12.D7(A16) U83.D7(A16) ; also on sheet 7 19
FLASH_ADDR17: U12.D8(A17) U83.D8(A17) ; also on sheet 7 19
FLASH_ADDR18: U12.A7(A18) U83.A7(A18) ; also on sheet 7 19
FLASH_ADDR19: U12.B7(A19) U83.B7(A19) ; also on sheet 7 19
FLASH_ADDR20: U12.C7(A20) U83.C7(A20) ; also on sheet 7 19
FLASH_ADDR21: U12.C8(A21) U83.C8(A21) ; also on sheet 7 19
FLASH_ADDR22: U12.A8(A22) U83.A8(A22) ; also on sheet 7 19
FLASH_ADDR23: U12.G1(NC(64M)/A23) U83.G1(NC(64M)/A23) ; also on sheet 7 19
FLASH_ADDR24: U12.H8(NC(64M,128M)/A24) U83.H8(NC(64M,128M)/A24) ; also on sheet 7 19
FLASH_ADDR25: U12.B6(NC/A25(512M)) U83.B6(NC/A25(512M)) ; also on sheet 7 19
FLASH_ADDR26: U12.B8(NC/A26(1G)) U83.B8(NC/A26(1G)) ; also on sheet 7 19
FLASH_ADVn: U12.F6(ADV#) U83.F6(ADV#) ; also on sheet 7 19
FLASH_CEn0: U12.B4(CE#) ; also on sheet 7 19
FLASH_CEn1: U83.B4(CE#) ; also on sheet 7 19
FLASH_CLK: U12.E6(CLK) U83.E6(CLK) ; also on sheet 7 19
FLASH_DATA0: U12.F2(D0) U83.F2(D0) ; also on sheet 7 19
FLASH_DATA1: U12.E2(D1) U83.E2(D1) ; also on sheet 7 19
FLASH_DATA2: U12.G3(D2) U83.G3(D2) ; also on sheet 7 19
FLASH_DATA3: U12.E4(D3) U83.E4(D3) ; also on sheet 7 19
FLASH_DATA4: U12.E5(D4) U83.E5(D4) ; also on sheet 7 19
FLASH_DATA5: U12.G5(D5) U83.G5(D5) ; also on sheet 7 19
FLASH_DATA6: U12.G6(D6) U83.G6(D6) ; also on sheet 7 19
FLASH_DATA7: U12.H7(D7) U83.H7(D7) ; also on sheet 7 19
FLASH_DATA8: U12.E1(D8) U83.E1(D8) ; also on sheet 7 19
FLASH_DATA9: U12.E3(D9) U83.E3(D9) ; also on sheet 7 19
FLASH_DATA10: U12.F3(D10) U83.F3(D10) ; also on sheet 7 19
FLASH_DATA11: U12.F4(D11) U83.F4(D11) ; also on sheet 7 19
FLASH_DATA12: U12.F5(D12) U83.F5(D12) ; also on sheet 7 19
FLASH_DATA13: U12.H5(D13) U83.H5(D13) ; also on sheet 7 19
FLASH_DATA14: U12.G7(D14) U83.G7(D14) ; also on sheet 7 19
FLASH_DATA15: U12.E7(D15) U83.E7(D15) ; also on sheet 7 19
FLASH_OEn: R73.2 U12.F8(OE#) U83.F8(OE#) ; also on sheet 7 19
FLASH_RDYBSYn0: R75.2 U12.F7(WAIT) ; also on sheet 7 19
FLASH_RDYBSYn1: R5297.2 U83.F7(WAIT) ; also on sheet 7 19
FLASH_RESETn: R77.2 U12.D4(RESET#) U83.D4(RESET#) ; also on sheet 7 19
FLASH_WEn: R74.2 U12.G8(WE#) U83.G8(WE#) ; also on sheet 7 19
FLASH_WPn: R76.2 U12.C6(WP#) U83.C6(WP#)
HILO_VDD: C146.1 C147.1 C148.1 J11.C7(VDD) J11.C9(VDD) J11.C11(VDD) J11.C13(VDD) J11.D6(VDD) J11.D8(VDD) J11.D10(VDD) J11.D12(VDD) J11.D14(VDD) J11.E7(VDD) J11.E9(VDD) J11.E11(VDD) J11.E13(VDD) J11.F6(VDD) J11.F8(VDD) J11.F10(VDD) ; also on sheet 42 46
HILO_VDDQ: C149.1 C150.1 C151.1 J11.F12(VDDQ) J11.F14(VDDQ) J11.G7(VDDQ) J11.G9(VDDQ) J11.G11(VDDQ) J11.G13(VDDQ) J11.H6(VDDQ) J11.H8(VDDQ) J11.H10(VDDQ) J11.H12(VDDQ) ; also on sheet 42 46
HILO_VREF: J11.H14(VREF) J11.J13(VREF) J11.K14(VREF) ; also on sheet 15 45
MDI_N0: J10.2(TD0_N) R79.2 U13.31(MDI0_N)
MDI_N1: J10.6(TD1_N) R81.2 U13.34(MDI1_N)
MDI_N2: J10.5(TD2_N) R83.2 U13.41(MDI2_N)
MDI_N3: J10.8(TD3_N) R85.2 U13.43(MDI3_N)
MDI_P0: J10.1(TD0_P) R78.2 U13.29(MDI0_P)
MDI_P1: J10.3(TD1_P) R80.2 U13.33(MDI1_P)
MDI_P2: J10.4(TD2_P) R82.2 U13.39(MDI2_P)
MDI_P3: J10.7(TD3_P) R84.2 U13.42(MDI3_P)
MEM_ADDR_CMD0: J11.F1(MEM_ADDR_CMD0) ; also on sheet 8
MEM_ADDR_CMD1: J11.H1(MEM_ADDR_CMD1) ; also on sheet 8
MEM_ADDR_CMD2: J11.F2(MEM_ADDR_CMD2) ; also on sheet 8
MEM_ADDR_CMD3: J11.G2(MEM_ADDR_CMD3) ; also on sheet 8
MEM_ADDR_CMD4: J11.H2(MEM_ADDR_CMD4) ; also on sheet 8
MEM_ADDR_CMD5: J11.J2(MEM_ADDR_CMD5) ; also on sheet 8
MEM_ADDR_CMD6: J11.K2(MEM_ADDR_CMD6) ; also on sheet 8
MEM_ADDR_CMD7: J11.G3(MEM_ADDR_CMD7) ; also on sheet 8
MEM_ADDR_CMD8: J11.J3(MEM_ADDR_CMD8) ; also on sheet 8
MEM_ADDR_CMD9: J11.L3(MEM_ADDR_CMD9) ; also on sheet 8
MEM_ADDR_CMD10: J11.E4(MEM_ADDR_CMD10) ; also on sheet 8
MEM_ADDR_CMD11: J11.F4(MEM_ADDR_CMD11) ; also on sheet 8
MEM_ADDR_CMD12: J11.G4(MEM_ADDR_CMD12) ; also on sheet 8
MEM_ADDR_CMD13: J11.H4(MEM_ADDR_CMD13) ; also on sheet 8
MEM_ADDR_CMD14: J11.J4(MEM_ADDR_CMD14) ; also on sheet 8
MEM_ADDR_CMD15: J11.K4(MEM_ADDR_CMD15) ; also on sheet 8
MEM_ADDR_CMD16: J11.M1(MEM_ADDR_CMD16) ; also on sheet 8
MEM_ADDR_CMD17: J11.M2(MEM_ADDR_CMD17) ; also on sheet 8
MEM_ADDR_CMD18: J11.N2(MEM_ADDR_CMD18) ; also on sheet 8
MEM_ADDR_CMD19: J11.L4(MEM_ADDR_CMD19) ; also on sheet 8
MEM_ADDR_CMD20: J11.P5(MEM_ADDR_CMD20) ; also on sheet 8
MEM_ADDR_CMD21: J11.M5(MEM_ADDR_CMD21) ; also on sheet 8
MEM_ADDR_CMD22: J11.P1(MEM_ADDR_CMD22) ; also on sheet 8
MEM_ADDR_CMD23: J11.R4(MEM_ADDR_CMD23) ; also on sheet 8
MEM_ADDR_CMD24: J11.M4(MEM_ADDR_CMD24) ; also on sheet 8
MEM_ADDR_CMD25: J11.R3(MEM_ADDR_CMD25) ; also on sheet 8
MEM_ADDR_CMD26: J11.L2(MEM_ADDR_CMD26) ; also on sheet 8
MEM_ADDR_CMD27: J11.K1(MEM_ADDR_CMD27) ; also on sheet 8
MEM_ADDR_CMD28: J11.P2(MEM_ADDR_CMD28) ; also on sheet 8
MEM_ADDR_CMD29: J11.N4(MEM_ADDR_CMD29) ; also on sheet 8
MEM_ADDR_CMD30: J11.P4(MEM_ADDR_CMD30) ; also on sheet 8
MEM_ADDR_CMD31: J11.N3(MEM_ADDR_CMD31) ; also on sheet 8
MEM_CLK_N: J11.V2(MEM_CLK_N) ; also on sheet 8
MEM_CLK_P: J11.V1(MEM_CLK_P) ; also on sheet 8
MEM_DMA0: J11.B10(MEM_DMA0) ; also on sheet 8
MEM_DMA1: J11.C4(MEM_DMA1) ; also on sheet 8
MEM_DMA2: J11.B17(MEM_DMA2) ; also on sheet 8
MEM_DMA3: J11.F17(MEM_DMA3) ; also on sheet 8
MEM_DMB0: J11.M16(MEM_DMB0) ; also on sheet 8
MEM_DMB1: J11.U16(MEM_DMB1) ; also on sheet 8
MEM_DMB2: J11.U11(MEM_DMB2) ; also on sheet 8
MEM_DMB3: J11.U6(MEM_DMB3) ; also on sheet 8
MEM_DQ_ADDR_CMD0: J11.R6(MEM_DQ_ADDR_CMD0) ; also on sheet 8
MEM_DQ_ADDR_CMD1: J11.T1(MEM_DQ_ADDR_CMD1) ; also on sheet 8
MEM_DQ_ADDR_CMD2: J11.R2(MEM_DQ_ADDR_CMD2) ; also on sheet 8
MEM_DQ_ADDR_CMD3: J11.T2(MEM_DQ_ADDR_CMD3) ; also on sheet 8
MEM_DQ_ADDR_CMD4: J11.U2(MEM_DQ_ADDR_CMD4) ; also on sheet 8
MEM_DQ_ADDR_CMD5: J11.U3(MEM_DQ_ADDR_CMD5) ; also on sheet 8
MEM_DQ_ADDR_CMD6: J11.T4(MEM_DQ_ADDR_CMD6) ; also on sheet 8
MEM_DQ_ADDR_CMD7: J11.U4(MEM_DQ_ADDR_CMD7) ; also on sheet 8
MEM_DQ_ADDR_CMD8: J11.T5(MEM_DQ_ADDR_CMD8) ; also on sheet 8
MEM_DQA0: J11.A4(MEM_DQA0) ; also on sheet 8
MEM_DQA1: J11.B4(MEM_DQA1) ; also on sheet 8
MEM_DQA2: J11.B5(MEM_DQA2) ; also on sheet 8
MEM_DQA3: J11.B6(MEM_DQA3) ; also on sheet 8
MEM_DQA4: J11.A8(MEM_DQA4) ; also on sheet 8
MEM_DQA5: J11.B8(MEM_DQA5) ; also on sheet 8
MEM_DQA6: J11.B9(MEM_DQA6) ; also on sheet 8
MEM_DQA7: J11.A10(MEM_DQA7) ; also on sheet 8
MEM_DQA8: J11.B1(MEM_DQA8) ; also on sheet 8
MEM_DQA9: J11.B2(MEM_DQA9) ; also on sheet 8
MEM_DQA10: J11.C2(MEM_DQA10) ; also on sheet 8
MEM_DQA11: J11.C3(MEM_DQA11) ; also on sheet 8
MEM_DQA12: J11.E3(MEM_DQA12) ; also on sheet 8
MEM_DQA13: J11.D4(MEM_DQA13) ; also on sheet 8
MEM_DQA14: J11.D1(MEM_DQA14) ; also on sheet 8
MEM_DQA15: J11.D2(MEM_DQA15) ; also on sheet 8
MEM_DQA16: J11.A12(MEM_DQA16) ; also on sheet 8
MEM_DQA17: J11.B12(MEM_DQA17) ; also on sheet 8
MEM_DQA18: J11.B13(MEM_DQA18) ; also on sheet 8
MEM_DQA19: J11.B14(MEM_DQA19) ; also on sheet 8
MEM_DQA20: J11.C15(MEM_DQA20) ; also on sheet 8
MEM_DQA21: J11.A16(MEM_DQA21) ; also on sheet 8
MEM_DQA22: J11.B16(MEM_DQA22) ; also on sheet 8
MEM_DQA23: J11.A18(MEM_DQA23) ; also on sheet 8
MEM_DQA24: J11.C16(MEM_DQA24) ; also on sheet 8
MEM_DQA25: J11.D16(MEM_DQA25) ; also on sheet 8
MEM_DQA26: J11.E16(MEM_DQA26) ; also on sheet 8
MEM_DQA27: J11.F16(MEM_DQA27) ; also on sheet 8
MEM_DQA28: J11.D17(MEM_DQA28) ; also on sheet 8
MEM_DQA29: J11.C18(MEM_DQA29) ; also on sheet 8
MEM_DQA30: J11.D18(MEM_DQA30) ; also on sheet 8
MEM_DQA31: J11.E18(MEM_DQA31) ; also on sheet 8
MEM_DQA32: J11.E2(MEM_DQA32) ; also on sheet 8
MEM_DQA33: J11.G16(MEM_DQA33) ; also on sheet 8
MEM_DQB0: J11.H16(MEM_DQB0) ; also on sheet 8
MEM_DQB1: J11.J16(MEM_DQB1) ; also on sheet 8
MEM_DQB2: J11.K16(MEM_DQB2) ; also on sheet 8
MEM_DQB3: J11.L16(MEM_DQB3) ; also on sheet 8
MEM_DQB4: J11.H17(MEM_DQB4) ; also on sheet 8
MEM_DQB5: J11.K17(MEM_DQB5) ; also on sheet 8
MEM_DQB6: J11.K18(MEM_DQB6) ; also on sheet 8
MEM_DQB7: J11.L18(MEM_DQB7) ; also on sheet 8
MEM_DQB8: J11.M17(MEM_DQB8) ; also on sheet 8
MEM_DQB9: J11.N18(MEM_DQB9) ; also on sheet 8
MEM_DQB10: J11.P17(MEM_DQB10) ; also on sheet 8
MEM_DQB11: J11.P18(MEM_DQB11) ; also on sheet 8
MEM_DQB12: J11.R18(MEM_DQB12) ; also on sheet 8
MEM_DQB13: J11.T16(MEM_DQB13) ; also on sheet 8
MEM_DQB14: J11.T17(MEM_DQB14) ; also on sheet 8
MEM_DQB15: J11.T18(MEM_DQB15) ; also on sheet 8
MEM_DQB16: J11.U15(MEM_DQB16) ; also on sheet 8
MEM_DQB17: J11.T14(MEM_DQB17) ; also on sheet 8
MEM_DQB18: J11.U14(MEM_DQB18) ; also on sheet 8
MEM_DQB19: J11.V14(MEM_DQB19) ; also on sheet 8
MEM_DQB20: J11.T13(MEM_DQB20) ; also on sheet 8
MEM_DQB21: J11.T12(MEM_DQB21) ; also on sheet 8
MEM_DQB22: J11.U12(MEM_DQB22) ; also on sheet 8
MEM_DQB23: J11.V12(MEM_DQB23) ; also on sheet 8
MEM_DQB24: J11.T10(MEM_DQB24) ; also on sheet 8
MEM_DQB25: J11.U10(MEM_DQB25) ; also on sheet 8
MEM_DQB26: J11.V10(MEM_DQB26) ; also on sheet 8
MEM_DQB27: J11.T9(MEM_DQB27) ; also on sheet 8
MEM_DQB28: J11.T8(MEM_DQB28) ; also on sheet 8
MEM_DQB29: J11.U8(MEM_DQB29) ; also on sheet 8
MEM_DQB30: J11.U7(MEM_DQB30) ; also on sheet 8
MEM_DQB31: J11.V6(MEM_DQB31) ; also on sheet 8
MEM_DQB32: J11.R16(MEM_DQB32) ; also on sheet 8
MEM_DQB33: J11.T6(MEM_DQB33) ; also on sheet 8
MEM_DQS_ADDR_CMD_N: J11.V5(MEM_DQS_ADDR_CMD_N) ; also on sheet 8
MEM_DQS_ADDR_CMD_P: J11.V4(MEM_DQS_ADDR_CMD_P) ; also on sheet 8
MEM_DQSA_N0: J11.A7(MEM_DQSA_N0) ; also on sheet 8
MEM_DQSA_N1: J11.A3(MEM_DQSA_N1) ; also on sheet 8
MEM_DQSA_N2: J11.A15(MEM_DQSA_N2) ; also on sheet 8
MEM_DQSA_N3: J11.G18(MEM_DQSA_N3) ; also on sheet 8
MEM_DQSA_P0: J11.A6(MEM_DQSA_P0) ; also on sheet 8
MEM_DQSA_P1: J11.A2(MEM_DQSA_P1) ; also on sheet 8
MEM_DQSA_P2: J11.A14(MEM_DQSA_P2) ; also on sheet 8
MEM_DQSA_P3: J11.F18(MEM_DQSA_P3) ; also on sheet 8
MEM_DQSB_N0: J11.J18(MEM_DQSB_N0) ; also on sheet 8
MEM_DQSB_N1: J11.V18(MEM_DQSB_N1) ; also on sheet 8
MEM_DQSB_N2: J11.V17(MEM_DQSB_N2) ; also on sheet 8
MEM_DQSB_N3: J11.V9(MEM_DQSB_N3) ; also on sheet 8
MEM_DQSB_P0: J11.H18(MEM_DQSB_P0) ; also on sheet 8
MEM_DQSB_P1: J11.U18(MEM_DQSB_P1) ; also on sheet 8
MEM_DQSB_P2: J11.V16(MEM_DQSB_P2) ; also on sheet 8
MEM_DQSB_P3: J11.V8(MEM_DQSB_P3) ; also on sheet 8
MEM_QKA_P0: J11.A11(MEM_QKA_N0) ; also on sheet 8
MEM_QKA_P1: J11.B18(MEM_QKA_N1) ; also on sheet 8
MEM_QKB_P0: J11.M18(MEM_QKB_N0) ; also on sheet 8
MEM_QKB_P1: J11.V13(MEM_QKB_N1) ; also on sheet 8
VBIAS_DP: C172.2 C173.2 R103.1 R105.1 R108.2 R110.2 R5359.1
N16838168: C131.2 R84.1 R85.1
N16838185: C129.2 R80.1 R81.1
N16838200: C128.2 R78.1 R79.1
N16838206: C130.2 R82.1 R83.1
N16838270: R92.2 U13.47(TRST_N)
N16838559: R86.1 X2.1(EN)
N16852954: F1.1 J12.20(DP_PWR)
N16854412: C169.2 R103.2 R5360.2 R5362.2
N16854416: C174.2 R110.1 R5361.2 R5363.2
N16854522: R5360.1 U16.6(A)
N16854558: R5361.1 U16.7(B)
N17814261: D2.C(CATHODE) R93.2
N17814263: D5.C(CATHODE) R96.2
N17814265: D3.C(CATHODE) R94.2
N17814267: D4.C(CATHODE) R95.2
N17814315: D6.C(CATHODE) R97.2
N18682325: F1.2 FB3.1

Not connected (* = marked no-connect by the designer): D7 5* 6*; D8 5* 6*; J11 G15(VDD_1.2V_SET)* H5(RFU2)* K5(RFU3)* L6(CONFIG0)* M6(CONFIG1)* N6(RFU4)* N15(VDDQ_1.1V_SET)* P16(VDDQ_1.2V_SET)* R7(RFU5)* R8(RFU6)*; J12 25(MH5)* 26(MH6)*; U12 E8(RFU3)* F1(RFU2)* G2(RFU1)* H1(RFU0)*; U13 2(RXCLK)* 3(RX_ER)* 4(TX_CLK)* 8(GTX_CLK)* 9(TX_EN)* 13(NC1)* 22(125CLK)* 37(HSDAC_P)* 38(HSDAC_N)* 44(TDI)* 46(TMS)* 49(TCK)* 50(TDO)* 51(NC2)* 54(XTAL2)* 56(SEL_FREQ)* 70(LED_DUPLEX)* 79(S_CLK_P)* 80(S_CLK_N)* 83(COL)* 84(CRS)* 86(RXD7)* 87(RXD6)* 89(RXD5)* 90(RXD4)* 91(RXD3)* 92(RXD1)* 93(RXD2)* 94(RX_DV)* 95(RXD0)*; U14 A2(IO_VL2)* C2(IO_VCC2)*; U15 5(A4)* 7(B4)*; U83 E8(RFU3)* F1(RFU2)* G2(RFU1)* H1(RFU0)*

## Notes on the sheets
sheet 20
- Flash Memory
- For Avalon Stream x16 Configuration
- FLASH 1-Gbit
- H = 1.20mm
  Place on Bottom side
- Use A10 SI board part for flash
- - When using a single x16 flash device a word consists of 16 data bits so addressing starts with FM_A1 mapped to address bit 1 in software.
sheet 21
- 10/100/1000 Ethernet Phy
- ENET RGMII INTERFACE
- SGMII Mode (default)
- ENET SGMII
- 88E1111-B2-CAA1C000 EOL
  88E1111-B2-NDC2C000 Pin Compatible Replacement
- DVDD = 1.0V
  DVDD = 1.2V
- Place near 88E1111 PHY
sheet 22
- HILO Connector Map
sheet 23
- HILO Memory Interface
- HILO MEMORY INTERFACE
- POWER CONTROL
- Place near
  HILO connector
  J14 VDD pins
- Place near
  HILO connector
  J14 VDDQ pins
sheet 24
- Display Port (x4)
- DISPLAYPORT INTERFACE
- H = 0.55mm
  Place on Bottom side
- H = 1.15mm
  Place on Bottom side
- Auxilary Channel -> Bidirctional LVDS 1Mbps/(720Mbps optional).
- Quartus IO Standard = BLVDS
       TX -> DIFF SSTL-1.8
       RX -> LVDS
  FogBugz Case 135234 & 147387
- H = 0.55mm
  Place on Bottom side
- H = 1.75mm
  Place on Bottom side
- 1)  TX uses diff sstl18 configuration, which is able to meet peak-to-peak differential voltage and common mode voltage spec for DP.
  2)  RX uses LVDS input, but user need to ensure pin voltage at NF receiver end is <1.9v.
      a.  If the channel is AC couple, then user need to choose the correct Vbias_RX so that Vpin < 1.9v. The spec is 0 – 2v, which is quite
  wide. Selecting Vbias_Rx at 2v region will cause NF device to have reliability issue.
      b.  If the channel is DC couple, user need to make sure TX common mode voltage + ground reference differences between Tx and Rx will not
  cause Vpin for NF to be higher than 1.9v.
